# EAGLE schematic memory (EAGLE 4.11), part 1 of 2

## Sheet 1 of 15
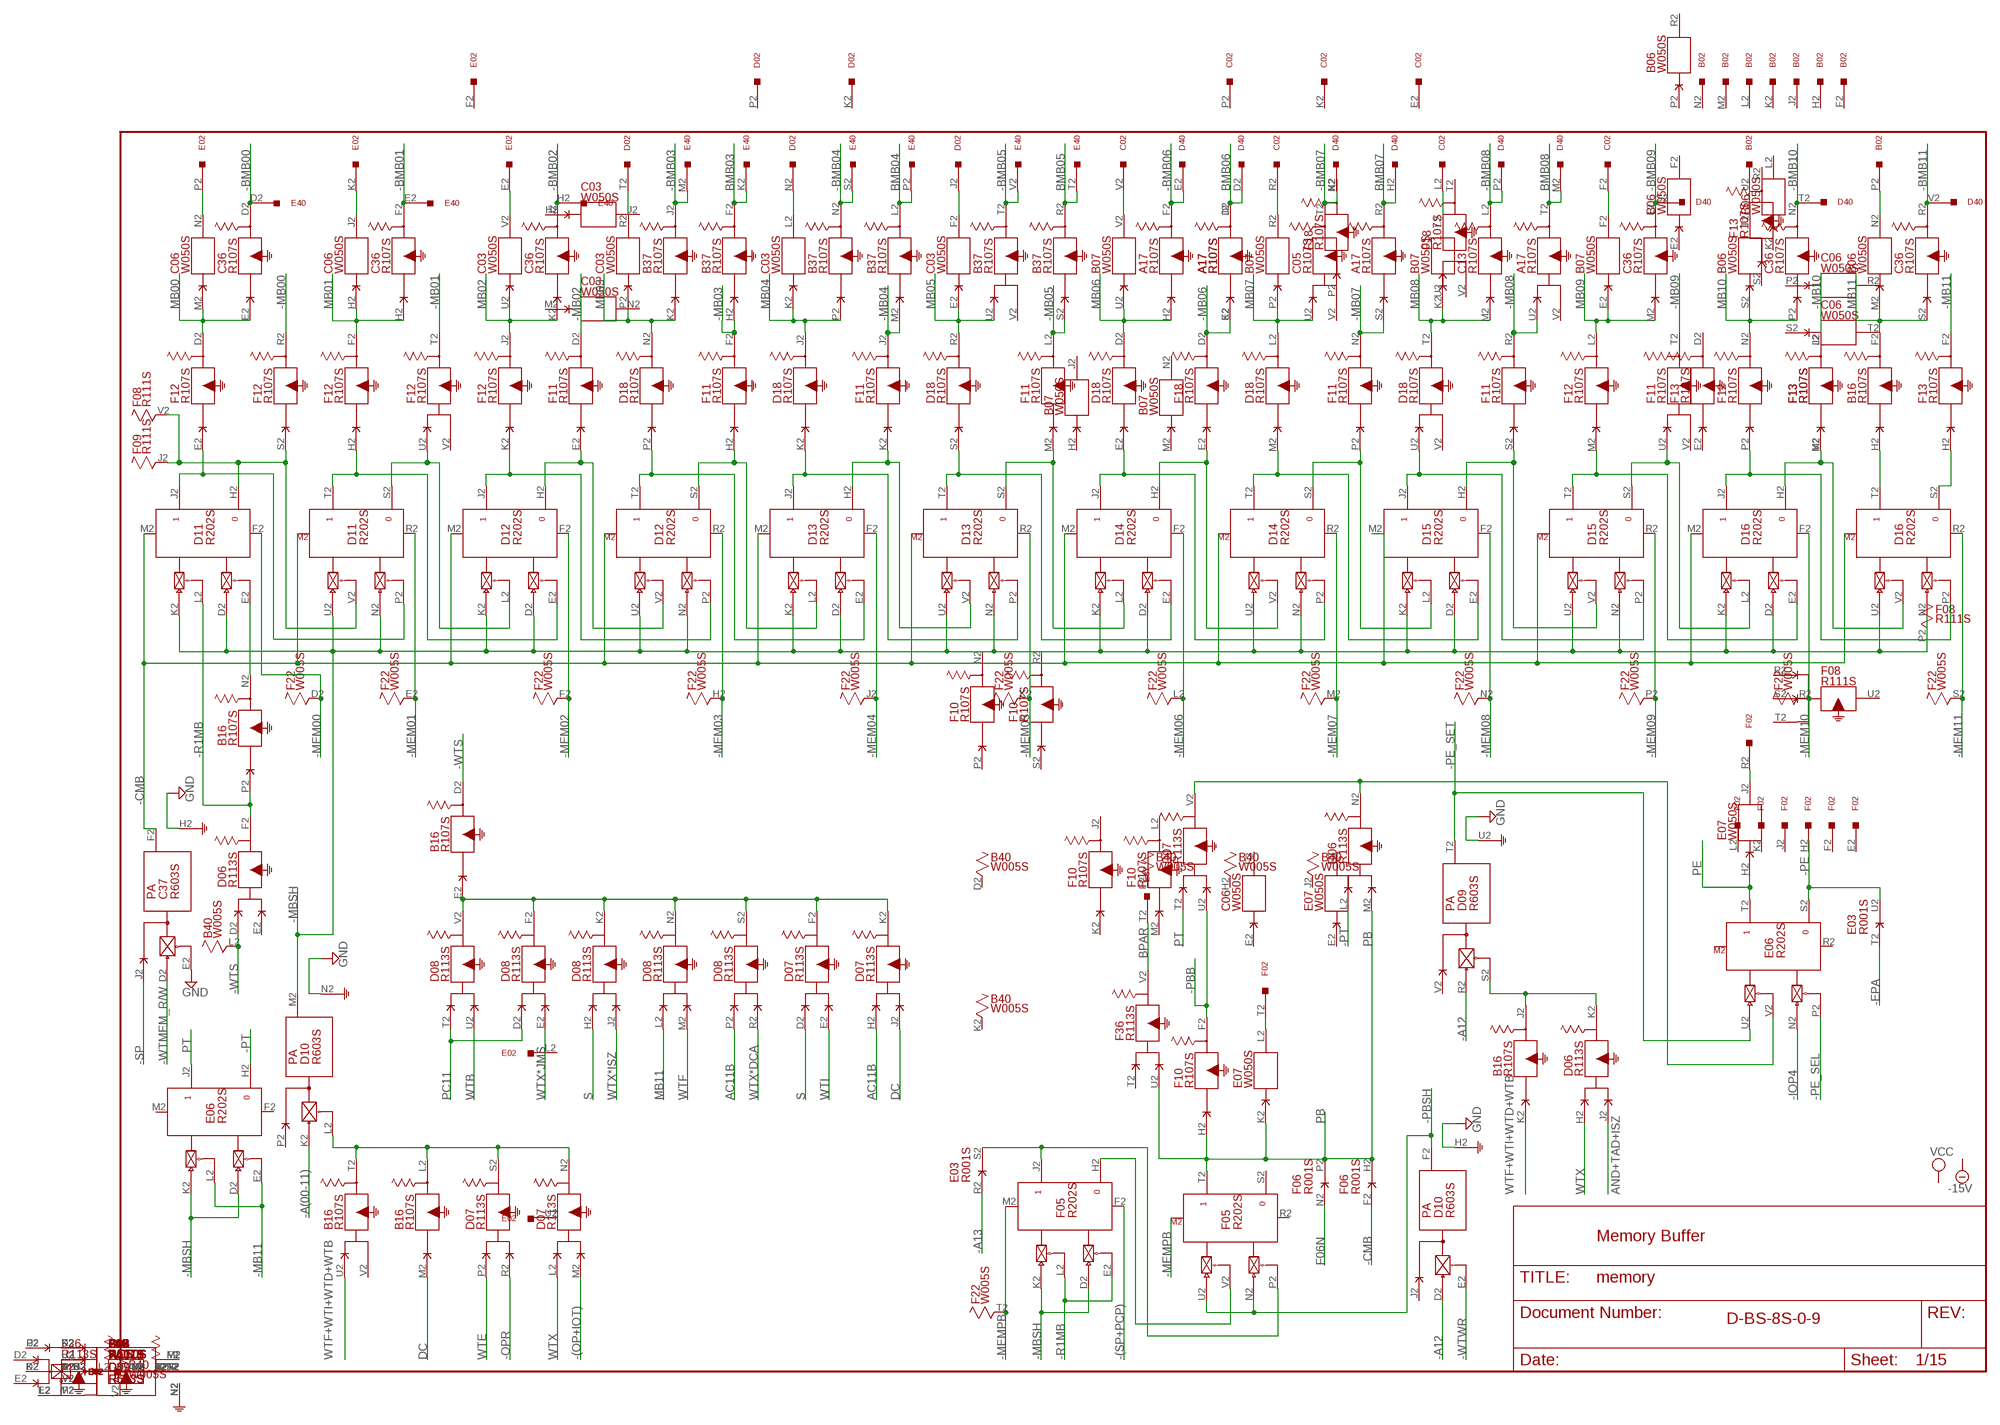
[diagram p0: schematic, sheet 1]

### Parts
A17  R107S  [H807S]
B02  W023S  [H807S]
B06  W050S  [H807S]
B07  W050S  [H807S]
B16  R107S  [H807S]
B37  R107S  [H807S]
B40  W005S  [H807S]
C02  W023S  [H807S]
C03  W050S  [H807S]
C05  R107S  [H807S]
C06  W050S  [H807S]
C13  R107S  [H807S]
C36  R107S  [H807S]
C37  R603S  [H807S]
D02  W023S  [H807S]
D06  R113S  [H807S]
D07  R113S  [H807S]
D08  R113S  [H807S]
D09  R603S  [H807S]
D10  R603S  [H807S]
D11  R202S  [H807S]
D12  R202S  [H807S]
D13  R202S  [H807S]
D14  R202S  [H807S]
D15  R202S  [H807S]
D16  R202S  [H807S]
D18  R107S  [H807S]
D40  W028S  [H807S]
E02  W023S  [H807S]
E03  R001S  [H807S]
E06  R202S  [H807S]
E07  W050S  [H807S]
E37  W028S  [H807S]
E40  W028S  [H807S]
F02  W023S  [H807S]
F05  R202S  [H807S]
F06  R001S  [H807S]
F08  R111S  [H807S]
F09  R111S  [H807S]
F10  R107S  [H807S]
F11  R107S  [H807S]
F12  R107S  [H807S]
F13  R107S  [H807S]
F18  R107S  [H807S]
F22  W005S  [H807S]
F36  R113S  [H807S]

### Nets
-(OP+IOT): D07.M2(N:I$2) ; also sheet 6,9
-(SP+PCP): F05.F2(J:RESET) ; also sheet 3,7,8,10,12,14,15
-A12: D09.R2(T:PU0) D10.D2(F:PU0) ; also sheet 3,4,6,8,10,12,15
-A13: E03.R2(S:D) ; also sheet 4,5,6,7,10,15
-A(00-11): D10.K2(M:PU0) ; also sheet 3,4,5,7,9,11,12
-BMB00: C36.D2(D:O$1) E40.D2
-BMB01: C36.F2(F:O$1) E40.E2
-BMB02: C36.J2(J:O$1) E40.H2
-BMB03: B37.J2(J:O$1) E40.M2
-BMB04: B37.N2(N:O$1) E40.S2
-BMB05: B37.T2(T:O$1) E40.V2
-BMB06: A17.F2(F:O$1) D40.E2
-BMB07: C05.T2(T:O$1) D40.K2
-BMB08: C13.L2(L:O$1) D40.P2
-BMB09: C36.L2(L:O$1) D40.S2
-BMB10: C36.N2(N:O$1) D40.T2
-BMB11: C36.R2(R:O$1) D40.V2
-CMB: C37.F2(F:O) D11.M2(J:SET) D12.M2(J:SET) D13.M2(J:SET) D14.M2(J:SET) D15.M2(J:SET) D16.M2(J:SET) F06.F2(H:D)
-EPA: E03.T2(U:D) ; also sheet 8
-IOP4: E06.N2(T:PU0) ; also sheet 10
-MB00: F12.R2(R:O$1) ; also sheet 2
-MB01: F12.T2(T:O$1) ; also sheet 2
-MB02: F11.D2(D:O$1) ; also sheet 2
-MB03: B37.H2(F:I$1) F11.F2(F:O$1) ; also sheet 2,10
-MB04: B37.M2(L:I$1) F11.J2(J:O$1) ; also sheet 2,5,10
-MB05: B37.S2(R:I$1) F11.L2(L:O$1) ; also sheet 2,6,10
-MB06: A17.E2(D:I$1) F18.D2(D:O$1) ; also sheet 2,6,7,10
-MB07: A17.S2(R:I$1) F11.N2(N:O$1) ; also sheet 2,6,10
-MB08: A17.U2(T:I$1) F11.R2(R:O$1) ; also sheet 2,3,10
-MB09: F11.T2(T:O$1) ; also sheet 2,10
-MB10: F13.L2(L:O$1) ; also sheet 2,9,10
-MB11: E06.E2(J:EN0) E06.L2(J:EN1) F13.F2(F:O$1) ; also sheet 2,9,10
-MBSH: D10.M2(M:O) D11.D2(J:PU0) D11.K2(J:PU1) D11.N2(T:PU0) D11.U2(T:PU1) D12.D2(J:PU0) D12.K2(J:PU1) D12.N2(T:PU0) D12.U2(T:PU1) D13.D2(J:PU0) D13.K2(J:PU1) D13.N2(T:PU0) D13.U2(T:PU1) D14.D2(J:PU0) D14.K2(J:PU1) D14.N2(T:PU0) D14.U2(T:PU1) D15.D2(J:PU0) D15.K2(J:PU1) D15.N2(T:PU0) D15.U2(T:PU1) D16.D2(J:PU0) D16.K2(J:PU1) D16.N2(T:PU0) D16.U2(T:PU1) E06.D2(J:PU0) E06.K2(J:PU1) F05.D2(J:PU0) F05.K2(J:PU1)
-MEM00: D11.F2(J:RESET) F22.D2 ; also sheet 2,15
-MEM01: D11.R2(T:RESET) F22.E2 ; also sheet 2,15
-MEM02: D12.F2(J:RESET) F22.F2 ; also sheet 2,15
-MEM03: D12.R2(T:RESET) F22.H2 ; also sheet 2,15
-MEM04: D13.F2(J:RESET) F22.J2 ; also sheet 2,15
-MEM05: D13.R2(T:RESET) F22.K2 ; also sheet 2,15
-MEM06: D14.F2(J:RESET) F22.L2 ; also sheet 2,15
-MEM07: D14.R2(T:RESET) F22.M2 ; also sheet 2,15
-MEM08: D15.F2(J:RESET) F22.N2 ; also sheet 2,15
-MEM09: D15.R2(T:RESET) F22.P2 ; also sheet 2,15
-MEM10: D16.F2(J:RESET) F22.R2 ; also sheet 2,15
-MEM11: D16.R2(T:RESET) F22.S2 ; also sheet 2,15
-MEMPB: F05.M2(J:SET) F22.T2 ; also sheet 2
-OPR: D07.R2(S:I$2) ; also sheet 9
-PBB: D07.U2(V:I$2) F10.F2(F:O$1) ; also sheet 2
-PBSH: D10.F2(F:O) F05.N2(T:PU0) F05.U2(T:PU1)
-PE: E03.U2(U:E) E06.S2 ; also sheet 10
-PE_SEL: E06.P2(T:EN0) ; also sheet 10
-PE_SET: D09.T2(T:O) E06.U2(T:PU1)
-PT: D06.L2(N:I$1) E06.H2
-R1MB: B16.P2(N:I$1) D06.F2(F:O$1) D11.L2(J:EN1) F05.E2(J:EN0) F05.L2(J:EN1)
-SP: C37.J2(F:I$1) ; also sheet 6,8
-WTMEM_R/W: C37.D2(F:PU0) ; also sheet 6,13
-WTS: B16.D2(D:O$1) B40.L2 D06.D2(F:I$1) ; also sheet 4,6
-WTWR: D10.E2(F:EN0) ; also sheet 6
AC11B: D07.H2(K:I$1) D08.P2(S:I$1) ; also sheet 7,12
AND+TAD+ISZ: D06.J2(K:I$2) ; also sheet 6,9
BMB03: B37.F2(F:O$1) E40.K2
BMB04: B37.L2(L:O$1) E40.P2
BMB05: B37.R2(R:O$1) E40.T2
BMB06: A17.D2(D:O$1) D40.D2
BMB07: A17.R2(R:O$1) D40.H2
BMB08: A17.T2(T:O$1) D40.M2
BPAR: E37.T2 F36.V2(V:O$1)
DC: B16.M2(L:I$1) D07.J2(K:I$2) ; also sheet 8,12
F06N: F06.N2(P:D)
GND [Supply]: C37.E2(F:EN0) C37.H2(F:G) D09.U2(T:G) D10.H2(F:G) D10.N2(M:G) ; also sheet 2,3,4,5,6,7,8,9,10,11,12,14,15
MB00: C06.M2(N:I$1) C36.E2(D:I$1) F12.D2(D:O$1)
MB01: C06.H2(J:I$1) C36.H2(F:I$1) F12.F2(F:O$1)
MB02: C03.U2(V:I$1) C36.K2(J:I$1) F12.J2(J:O$1)
MB03: B37.K2(J:I$1) C03.P2(R:I$1) D18.N2(N:O$1)
MB04: B37.P2(N:I$1) C03.K2(L:I$1) D18.J2(J:O$1) ; also sheet 12
MB05: B37.U2(T:I$1) C03.E2(F:I$1) D18.R2(R:O$1) ; also sheet 3,9,10
MB06: A17.H2(F:I$1) B07.U2(V:I$1) D18.D2(D:O$1) ; also sheet 3,7,9
MB07: B07.P2(R:I$1) C05.U2(T:I$1) D18.L2(L:O$1) ; also sheet 3,9
MB08: B07.K2(L:I$1) C13.M2(L:I$1) D18.T2(T:O$1) ; also sheet 3,6,9
MB09: B07.E2(F:I$1) C36.M2(L:I$1) F12.L2(L:O$1) ; also sheet 3,9
MB10: B06.S2(T:I$1) C36.P2(N:I$1) F12.N2(N:O$1) ; also sheet 8,9
MB11: B06.M2(N:I$1) B16.F2(F:O$1) C36.S2(R:I$1) D08.L2(N:I$1) ; also sheet 5,6,7,9,12
N$1: D11.J2 D11.P2(T:EN0) F12.E2(D:I$1)
N$2: C06.N2(N:O$1) E02.P2
N$3: D11.H2 D11.V2(T:EN1) F08.V2 F09.J2 F12.S2(R:I$1)
N$4: D11.T2 D12.E2(J:EN0) F12.H2(F:I$1)
N$5: B16.E2(D:I$1) D07.F2(F:O$1) D07.K2(K:O$1) D08.F2(F:O$1) D08.K2(K:O$1) D08.N2(N:O$1) D08.S2(S:O$1) D08.V2(V:O$1)
N$6: D12.J2 D12.P2(T:EN0) F12.K2(J:I$1)
N$7: D12.T2 D13.E2(J:EN0) D18.P2(N:I$1)
N$8: D13.J2 D13.P2(T:EN0) D18.K2(J:I$1)
N$9: D13.T2 D14.E2(J:EN0) D18.S2(R:I$1)
N$10: D14.J2 D14.P2(T:EN0) D18.E2(D:I$1)
N$11: D14.T2 D15.E2(J:EN0) D18.M2(L:I$1)
N$12: D15.J2 D15.P2(T:EN0) D18.U2(T:I$1)
N$13: D15.H2 D15.V2(T:EN1) F11.S2(R:I$1)
N$14: D14.S2 D15.L2(J:EN1) F11.P2(N:I$1)
N$15: D14.H2 D14.V2(T:EN1) F18.E2(D:I$1)
N$16: D13.S2 D14.L2(J:EN1) F11.M2(L:I$1)
N$17: D15.T2 D16.E2(J:EN0) F12.M2(L:I$1)
N$18: D15.S2 D16.L2(J:EN1) F11.U2(T:I$1)
N$19: D16.J2 D16.P2(T:EN0) F12.P2(N:I$1)
N$20: D13.H2 D13.V2(T:EN1) F11.K2(J:I$1)
N$21: D12.S2 D13.L2(J:EN1) F11.H2(F:I$1)
N$22: D12.H2 D12.V2(T:EN1) F11.E2(D:I$1)
N$23: D11.S2 D12.L2(J:EN1) F12.U2(T:I$1)
N$24: D16.H2 D16.V2(T:EN1) F13.M2(L:I$1)
N$25: B16.H2(F:I$1) D16.T2
N$26: D16.S2 F13.H2(F:I$1)
N$27: C06.J2(J:O$1) E02.K2
N$28: C03.V2(V:O$1) E02.E2
N$29: C03.R2(R:O$1) D02.T2
N$30: C03.L2(L:O$1) D02.N2
N$31: C03.F2(F:O$1) D02.J2
N$32: B07.V2(V:O$1) C02.V2
N$33: B07.R2(R:O$1) C02.R2
N$34: B07.L2(L:O$1) C02.L2
N$35: B07.F2(F:O$1) C02.F2
N$36: B02.U2 B06.T2(T:O$1)
N$37: B02.P2 B06.N2(N:O$1)
N$38: B16.L2(L:O$1) B16.T2(T:O$1) D07.N2(N:O$1) D07.S2(S:O$1) D10.L2(M:EN0)
N$39: B16.N2(N:O$1) D11.E2(J:EN0)
N$40: B16.J2(J:O$1) D06.K2(K:O$1) D09.S2(T:EN0)
N$41: E07.J2(J:O$1) F02.R2
N$42: D06.N2(N:O$1) D07.V2(V:O$1) E06.V2(T:EN1)
N$44: E07.L2(L:O$1) F02.T2
N$46: F05.H2 F05.V2(T:EN1)
N$47: E03.S2(S:E) F05.J2 F05.P2(T:EN0)
PB: D06.M2(N:I$2) E07.K2(L:I$1) F05.T2 F06.H2(H:E) F06.P2(P:E) F10.H2(F:I$1) F36.U2(V:I$2)
PC11: D08.D2(F:I$1) D08.T2(V:I$1) ; also sheet 5,7,11
PE: E06.T2 E07.H2(J:I$1) ; also sheet 10
PT: D07.T2(V:I$1) E06.J2
S: D07.D2(F:I$1) D08.H2(K:I$1) ; also sheet 5,7,11,12
WTB: D08.U2(V:I$2) ; also sheet 6
WTE: D07.P2(S:I$1) ; also sheet 3,6,8
WTF: D08.M2(N:I$2) ; also sheet 3,5,6,8,10,12
WTF+WTI+WTD+WTB: B16.K2(J:I$1) B16.U2(T:I$1) ; also sheet 6
WTI: D07.E2(F:I$2) ; also sheet 6
WTX: D06.H2(K:I$1) D07.L2(N:I$1) ; also sheet 3,6,7,10,12,15
WTX*DCA: D08.R2(S:I$2) ; also sheet 6
WTX*ISZ: D08.J2(K:I$2) ; also sheet 6
WTX*JMS: D08.E2(F:I$2) ; also sheet 6
Unconnected: B02.A2 B02.B2 B02.C2 B02.S2 B40.R2 C02.A2 C02.B2 C02.C2 C02.D2 C02.J2 C02.N2 C02.T2 C36.T2(T:O$1) C36.U2(T:I$1) C36.V2(T:I$2) D02.A2 D02.B2 D02.C2 D02.D2 D02.H2 D02.M2 D02.S2 D02.V2 E02.A2 E02.B2 E02.C2 E02.J2 E02.N2 E06.F2(J:RESET) E06.M2(J:SET) E06.R2(T:RESET) E07.P2(R:I$1) E07.R2(R:O$1) E07.S2(T:I$1) E07.T2(T:O$1) F02.A2 F02.B2 F02.C2 F02.N2 F02.P2 F02.S2 F02.U2 F05.R2(T:RESET) F05.S2 F11.V2(T:I$2) F12.V2(T:I$2) F22.V2

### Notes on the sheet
- Memory Buffer
- D-BS-8S-0-9

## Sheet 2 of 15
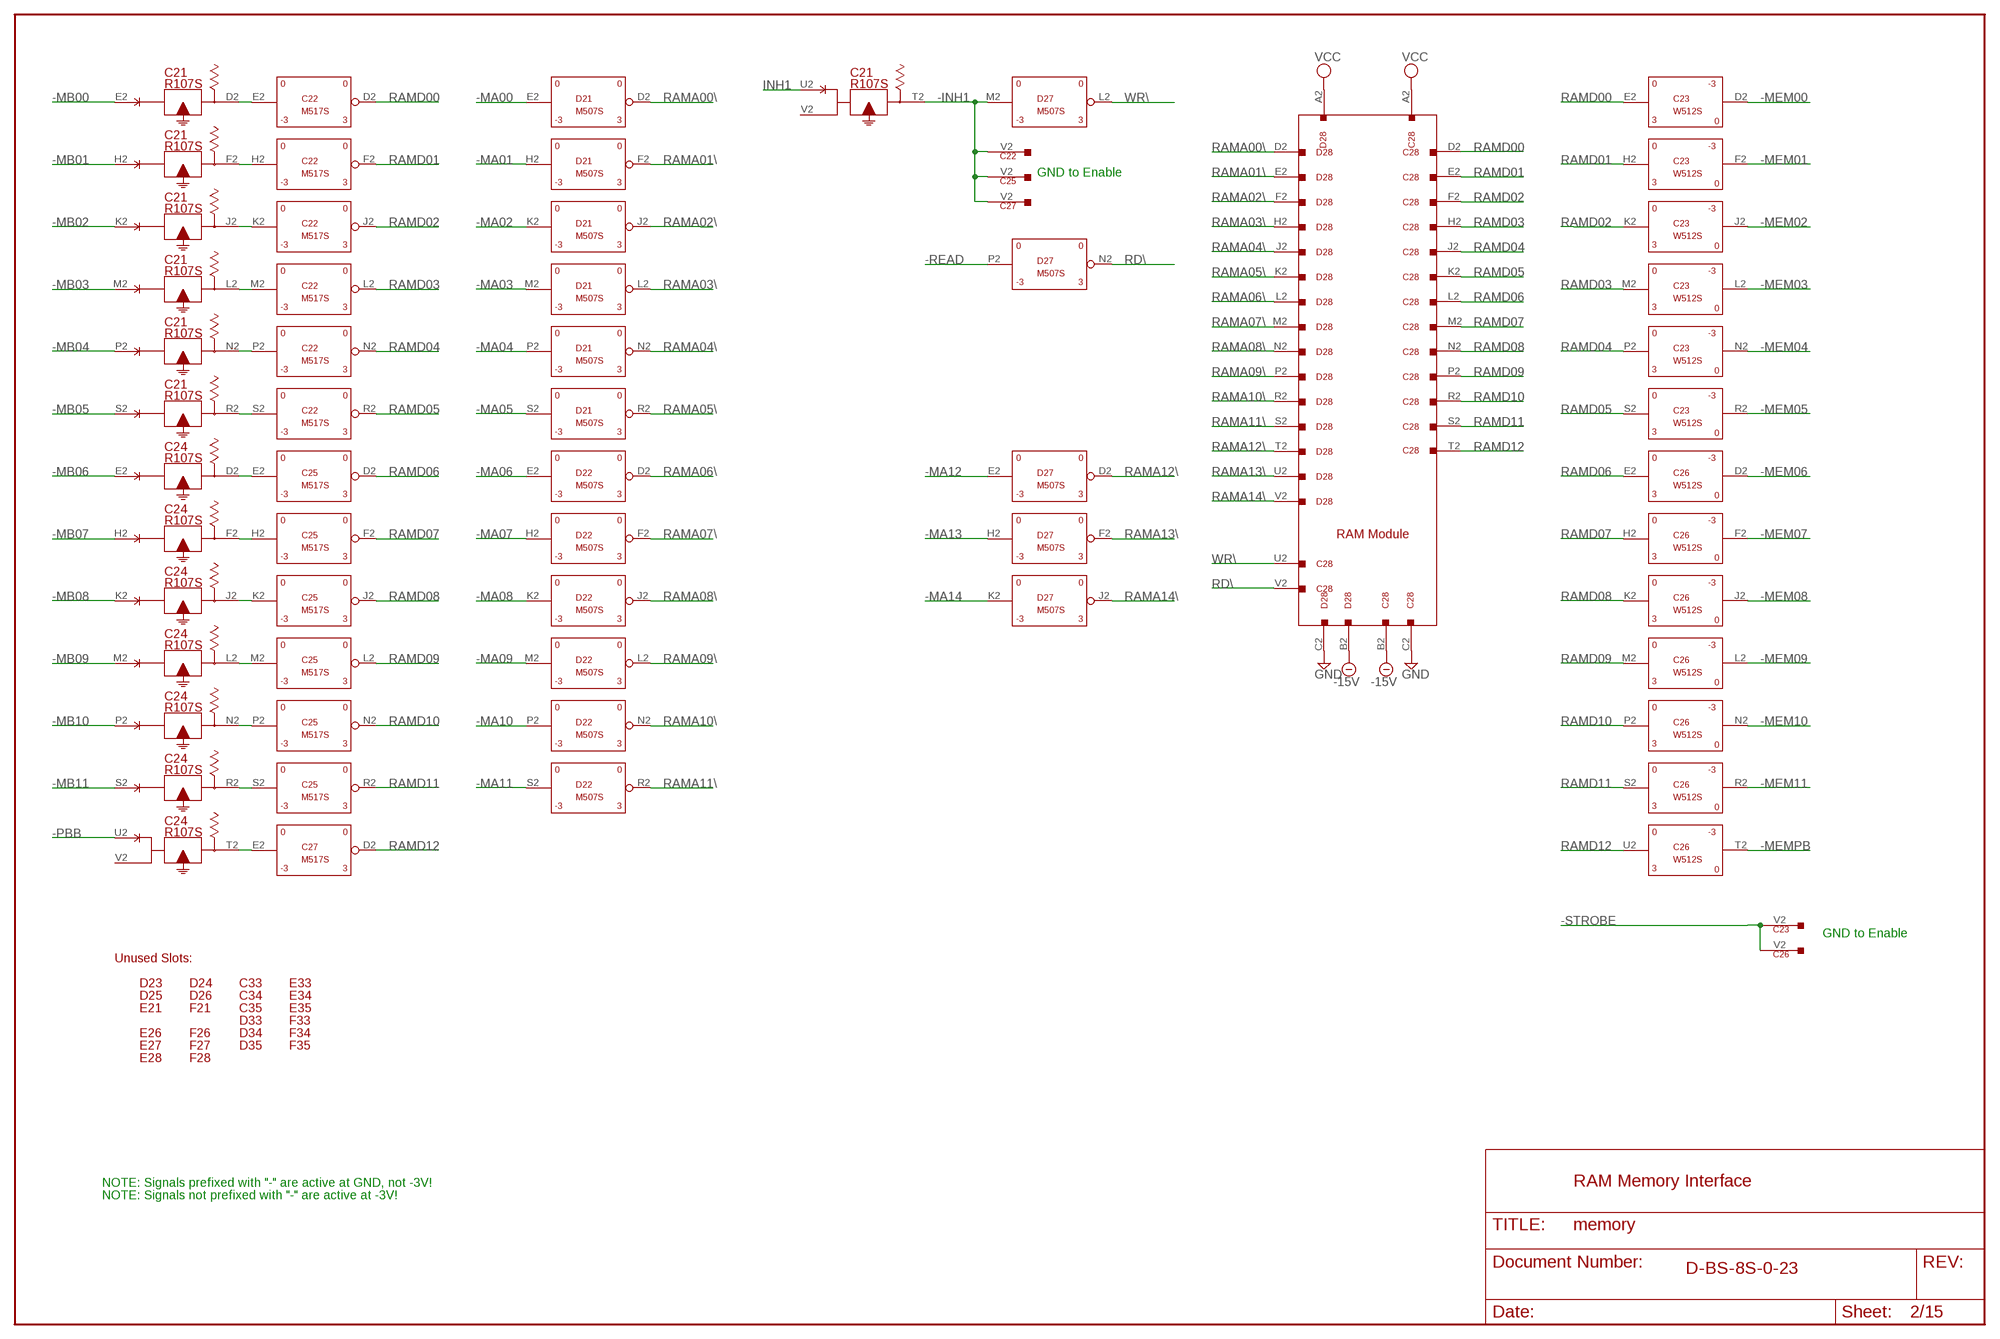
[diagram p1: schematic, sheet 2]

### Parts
C21  R107S  [H807S]
C22  M517S  [H807S]
C23  W512S  [H807S]
C24  R107S  [H807S]
C25  M517S  [H807S]
C26  W512S  [H807S]
C27  M517S  [H807S]
C28  W023S  [H807S]
C33  EMPTYS  [H807S]
C34  EMPTYS  [H807S]
C35  EMPTYS  [H807S]
D21  M507S  [H807S]
D22  M507S  [H807S]
D23  EMPTYS  [H807S]
D24  EMPTYS  [H807S]
D25  EMPTYS  [H807S]
D26  EMPTYS  [H807S]
D27  M507S  [H807S]
D28  W023S  [H807S]
D33  EMPTYS  [H807S]
D34  EMPTYS  [H807S]
D35  EMPTYS  [H807S]
E21  EMPTYS  [H807S]
E26  EMPTYS  [H807S]
E27  EMPTYS  [H807S]
E28  EMPTYS  [H807S]
E33  EMPTYS  [H807S]
E34  EMPTYS  [H807S]
E35  EMPTYS  [H807S]
F21  EMPTYS  [H807S]
F26  EMPTYS  [H807S]
F27  EMPTYS  [H807S]
F28  EMPTYS  [H807S]
F33  EMPTYS  [H807S]
F34  EMPTYS  [H807S]
F35  EMPTYS  [H807S]

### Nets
-15V [Supply]: C28.B2 D28.B2
-INH1: C21.T2(T:O$1) C22.V2 C25.V2 C27.V2 D27.M2(L:IN)
-MA00: D21.E2(D:IN) ; also sheet 5,15
-MA01: D21.H2(F:IN) ; also sheet 5,15
-MA02: D21.K2(J:IN) ; also sheet 5,15
-MA03: D21.M2(L:IN) ; also sheet 5,15
-MA04: D21.P2(N:IN) ; also sheet 5,6,15
-MA05: D21.S2(R:IN) ; also sheet 5,15
-MA06: D22.E2(D:IN) ; also sheet 5,15
-MA07: D22.H2(F:IN) ; also sheet 5,15
-MA08: D22.K2(J:IN) ; also sheet 5,15
-MA09: D22.M2(L:IN) ; also sheet 5,15
-MA10: D22.P2(N:IN) ; also sheet 5,15
-MA11: D22.S2(R:IN) ; also sheet 5,15
-MA12: D27.E2(D:IN)
-MA13: D27.H2(F:IN)
-MA14: D27.K2(J:IN)
-MB00: C21.E2(D:I$1) ; also sheet 1
-MB01: C21.H2(F:I$1) ; also sheet 1
-MB02: C21.K2(J:I$1) ; also sheet 1
-MB03: C21.M2(L:I$1) ; also sheet 1,10
-MB04: C21.P2(N:I$1) ; also sheet 1,5,10
-MB05: C21.S2(R:I$1) ; also sheet 1,6,10
-MB06: C24.E2(D:I$1) ; also sheet 1,6,7,10
-MB07: C24.H2(F:I$1) ; also sheet 1,6,10
-MB08: C24.K2(J:I$1) ; also sheet 1,3,10
-MB09: C24.M2(L:I$1) ; also sheet 1,10
-MB10: C24.P2(N:I$1) ; also sheet 1,9,10
-MB11: C24.S2(R:I$1) ; also sheet 1,9,10
-MEM00: C23.D2(OUT) ; also sheet 1,15
-MEM01: C23.F2(OUT) ; also sheet 1,15
-MEM02: C23.J2(OUT) ; also sheet 1,15
-MEM03: C23.L2(OUT) ; also sheet 1,15
-MEM04: C23.N2(OUT) ; also sheet 1,15
-MEM05: C23.R2(OUT) ; also sheet 1,15
-MEM06: C26.D2(OUT) ; also sheet 1,15
-MEM07: C26.F2(OUT) ; also sheet 1,15
-MEM08: C26.J2(OUT) ; also sheet 1,15
-MEM09: C26.L2(OUT) ; also sheet 1,15
-MEM10: C26.N2(OUT) ; also sheet 1,15
-MEM11: C26.R2(OUT) ; also sheet 1,15
-MEMPB: C26.T2(OUT) ; also sheet 1
-PBB: C24.U2(T:I$1) ; also sheet 1
-READ: D27.P2(N:IN) ; also sheet 13
-STROBE: C23.V2 C26.V2 ; also sheet 13
GND [Supply]: C28.C2 D28.C2 ; also sheet 1,3,4,5,6,7,8,9,10,11,12,14,15
INH1: C21.U2(T:I$1) ; also sheet 13
N$49: C24.D2(D:O$1) C25.E2(D:IN)
N$50: C21.R2(R:O$1) C22.S2(R:IN)
N$51: C21.N2(N:O$1) C22.P2(N:IN)
N$52: C21.L2(L:O$1) C22.M2(L:IN)
N$55: C21.J2(J:O$1) C22.K2(J:IN)
N$56: C21.F2(F:O$1) C22.H2(F:IN)
N$57: C21.D2(D:O$1) C22.E2(D:IN)
N$58: C24.F2(F:O$1) C25.H2(F:IN)
N$59: C24.J2(J:O$1) C25.K2(J:IN)
N$60: C24.L2(L:O$1) C25.M2(L:IN)
N$61: C24.N2(N:O$1) C25.P2(N:IN)
N$62: C24.R2(R:O$1) C25.S2(R:IN)
N$63: C24.T2(T:O$1) C27.E2(D:IN)
RAMA00\: D21.D2(D:OUT) D28.D2
RAMA01\: D21.F2(F:OUT) D28.E2
RAMA02\: D21.J2(J:OUT) D28.F2
RAMA03\: D21.L2(L:OUT) D28.H2
RAMA04\: D21.N2(N:OUT) D28.J2
RAMA05\: D21.R2(R:OUT) D28.K2
RAMA06\: D22.D2(D:OUT) D28.L2
RAMA07\: D22.F2(F:OUT) D28.M2
RAMA08\: D22.J2(J:OUT) D28.N2
RAMA09\: D22.L2(L:OUT) D28.P2
RAMA10\: D22.N2(N:OUT) D28.R2
RAMA11\: D22.R2(R:OUT) D28.S2
RAMA12\: D27.D2(D:OUT) D28.T2
RAMA13\: D27.F2(F:OUT) D28.U2
RAMA14\: D27.J2(J:OUT) D28.V2
RAMD00: C22.D2(D:OUT) C23.E2(IN) C28.D2
RAMD01: C22.F2(F:OUT) C23.H2(IN) C28.E2
RAMD02: C22.J2(J:OUT) C23.K2(IN) C28.F2
RAMD03: C22.L2(L:OUT) C23.M2(IN) C28.H2
RAMD04: C22.N2(N:OUT) C23.P2(IN) C28.J2
RAMD05: C22.R2(R:OUT) C23.S2(IN) C28.K2
RAMD06: C25.D2(D:OUT) C26.E2(IN) C28.L2
RAMD07: C25.F2(F:OUT) C26.H2(IN) C28.M2
RAMD08: C25.J2(J:OUT) C26.K2(IN) C28.N2
RAMD09: C25.L2(L:OUT) C26.M2(IN) C28.P2
RAMD10: C25.N2(N:OUT) C26.P2(IN) C28.R2
RAMD11: C25.R2(R:OUT) C26.S2(IN) C28.S2
RAMD12: C26.U2(IN) C27.D2(D:OUT) C28.T2
RD\: C28.V2 D27.N2(N:OUT)
VCC [Supply]: C28.A2 D28.A2
WR\: C28.U2 D27.L2(L:OUT)
Unconnected: C21.V2(T:I$2) C23.T2(OUT) C23.U2(IN) C24.V2(T:I$2) C27.F2(F:OUT) C27.H2(F:IN) C27.J2(J:OUT) C27.K2(J:IN) C27.L2(L:OUT) C27.M2(L:IN) C27.N2(N:OUT) C27.P2(N:IN) C27.R2(R:OUT) C27.S2(R:IN) D27.R2(R:OUT) D27.S2(R:IN)

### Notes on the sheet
- GND to Enable
- RAM Module
- GND to Enable
- Unused Slots:
- NOTE: Signals prefixed with "-" are active at GND, not -3V! | RAM Memory Interface
- NOTE: Signals not prefixed with "-" are active at -3V!
- D-BS-8S-0-23

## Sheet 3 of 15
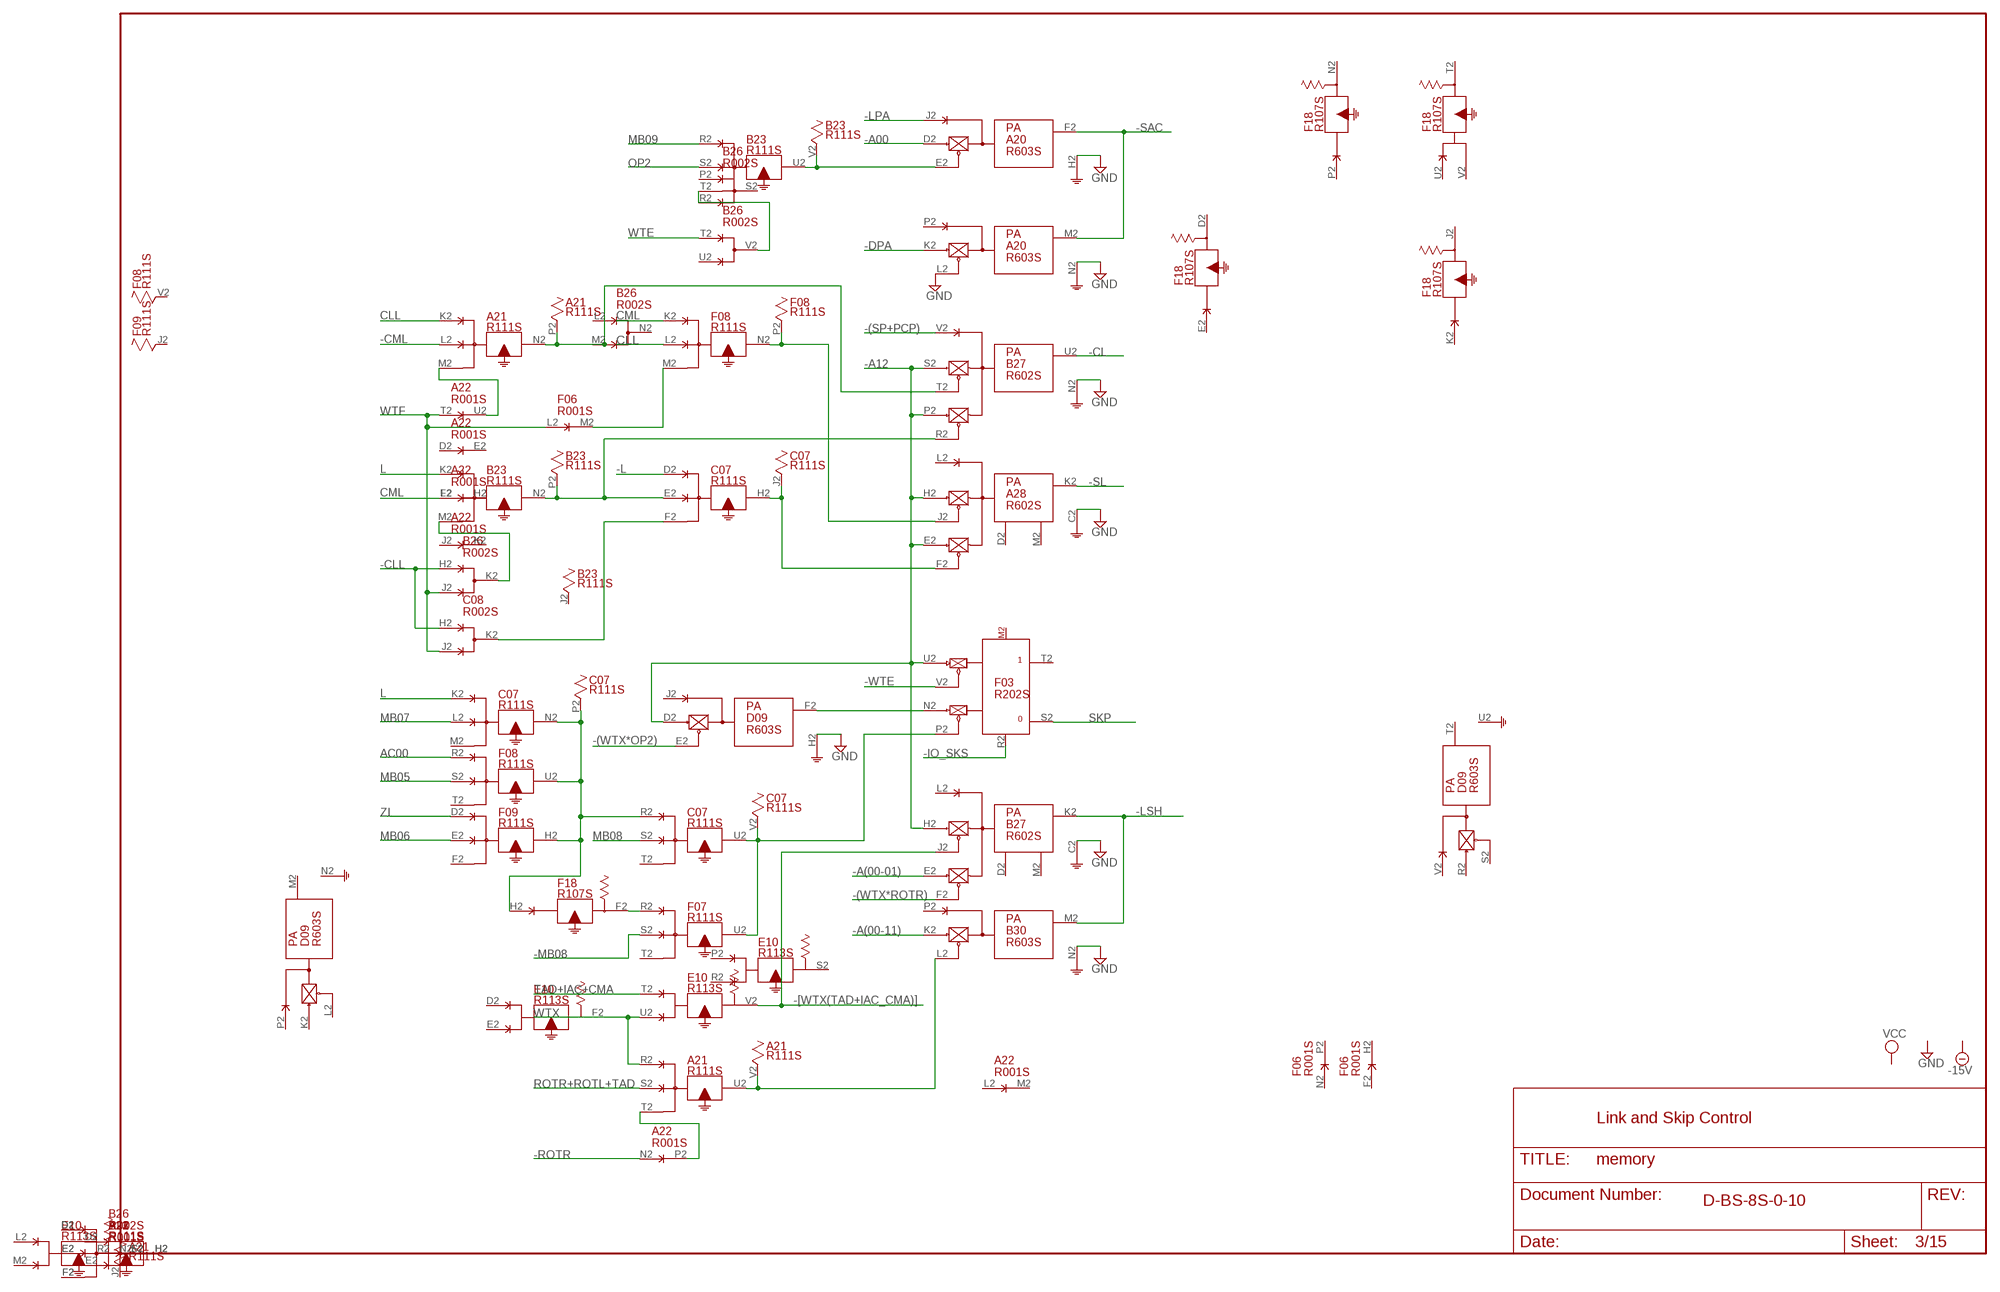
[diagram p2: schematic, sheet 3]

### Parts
A20  R603S  [H807S]
A21  R111S  [H807S]
A22  R001S  [H807S]
A28  R602S  [H807S]
B23  R111S  [H807S]
B26  R002S  [H807S]
B27  R602S  [H807S]
B30  R603S  [H807S]
C07  R111S  [H807S]
C08  R002S  [H807S]
E10  R113S  [H807S]
F03  R202S  [H807S]
F07  R111S  [H807S]

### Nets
-(SP+PCP): B27.V2(U:L) ; also sheet 1,7,8,10,12,14,15
-(WTX*OP2): D09.E2(F:EN0) ; also sheet 6,7
-(WTX*ROTR): B27.F2(K:F) ; also sheet 6,12
-[WTX(TAD+IAC_CMA)]: B27.J2(K:J) E10.V2(V:O$1)
-A00: A20.D2(F:PU0) ; also sheet 4,5,9,10,14,15
-A12: A28.E2(K:E) A28.H2(K:H) B27.H2(K:H) B27.P2(U:E) B27.S2(U:H) D09.D2(F:PU0) F03.U2(T:PU1) ; also sheet 1,4,6,8,10,12,15
-A(00-01): B27.E2(K:E) ; also sheet 4,12
-A(00-11): B30.K2(M:PU0) ; also sheet 1,4,5,7,9,11,12
-CL: B27.U2(U:K) ; also sheet 12
-CLL: B26.H2(K:D) C08.H2(K:D) ; also sheet 9
-CML: A21.L2(N:I$2) ; also sheet 9
-DPA: A20.K2(M:PU0) ; also sheet 8
-IO_SKS: F03.R2(T:RESET) ; also sheet 10
-L: C07.D2(H:I$1) ; also sheet 12
-LPA: A20.J2(F:I$1) ; also sheet 8
-LSH: B27.K2(K:K) B30.M2(M:O) ; also sheet 12
-MB08: F07.S2(U:I$2) ; also sheet 1,2,10
-ROTR: A22.N2(P:D) ; also sheet 9
-SAC: A20.F2(F:O) A20.M2(M:O) ; also sheet 8
-SL: A28.K2(K:K) ; also sheet 12
-WTE: F03.V2(T:EN1) ; also sheet 6
AC00: F08.R2(U:I$1) ; also sheet 12
CLL: A21.K2(N:I$1) F08.L2(N:I$2) ; also sheet 9
CML: B23.L2(N:I$2) F08.K2(N:I$1) ; also sheet 9
GND [Supply]: A20.H2(F:G) A20.L2(M:EN0) A20.N2(M:G) A28.C2(K:GND) B27.C2(K:GND) B27.N2(U:C) B30.N2(M:G) D09.H2(F:G) ; also sheet 1,2,4,5,6,7,8,9,10,11,12,14,15
L: B23.K2(N:I$1) C07.K2(N:I$1) ; also sheet 7,12
MB05: F08.S2(U:I$2) ; also sheet 1,9,10
MB06: F09.E2(H:I$2) ; also sheet 1,7,9
MB07: C07.L2(N:I$2) ; also sheet 1,9
MB08: C07.S2(U:I$2) ; also sheet 1,6,9
MB09: B23.R2(U:I$1) ; also sheet 1,9
N$48: A20.E2(F:EN0) B23.U2(U:O$1) B23.V2
N$53: B23.T2(U:I$3) B26.V2(V:F)
N$54: A28.J2(K:J) F08.N2(N:O$1) F08.P2
N$64: A21.N2(N:O$1) A21.P2 B27.T2(U:J)
N$65: B23.N2(N:O$1) B23.P2 B27.R2(U:F) C07.E2(H:I$2)
N$66: A28.F2(K:F) C07.H2(H:O$1) C07.J2
N$67: B23.M2(N:I$3) B26.K2(K:F)
N$68: F06.M2(M:E) F08.M2(N:I$3)
N$69: C07.F2(H:I$3) C08.K2(K:F)
N$71: D09.F2(F:O) F03.N2(T:PU0)
N$72: C07.U2(U:O$1) C07.V2 F03.P2(T:EN0) F07.U2(U:O$1)
N$73: F07.R2(U:I$1) F18.F2(F:O$1)
N$74: C07.N2(N:O$1) C07.P2 C07.R2(U:I$1) F08.U2(U:O$1) F09.H2(H:O$1) F18.H2(F:I$1)
N$75: A21.U2(U:O$1) A21.V2 B30.L2(M:EN0)
N$76: A21.T2(U:I$3) A22.P2(P:E)
N$79: A21.M2(N:I$3) A22.U2(U:E)
OP2: B23.S2(U:I$2) ; also sheet 6,7,8,9,12
ROTR+ROTL+TAD: A21.S2(U:I$2) ; also sheet 9,12
SKP: F03.S2 ; also sheet 9
TAD+IAC+CMA: E10.T2(V:I$1) ; also sheet 9,12
WTE: B26.T2(V:D) ; also sheet 1,6,8
WTF: A22.T2(U:D) B26.J2(K:E) C08.J2(K:E) F06.L2(M:D) ; also sheet 1,5,6,8,10,12
WTX: A21.R2(U:I$1) E10.U2(V:I$2) ; also sheet 1,6,7,10,12,15
ZI: F09.D2(H:I$1) ; also sheet 7,9
Unconnected: B27.D2(K:D) B27.L2(K:L) B27.M2(K:M) C07.M2(N:I$3) C07.T2(U:I$3) C08.L2(N:D) C08.M2(N:E) C08.N2(N:F) F07.P2 F07.V2

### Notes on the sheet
- Link and Skip Control
- D-BS-8S-0-10

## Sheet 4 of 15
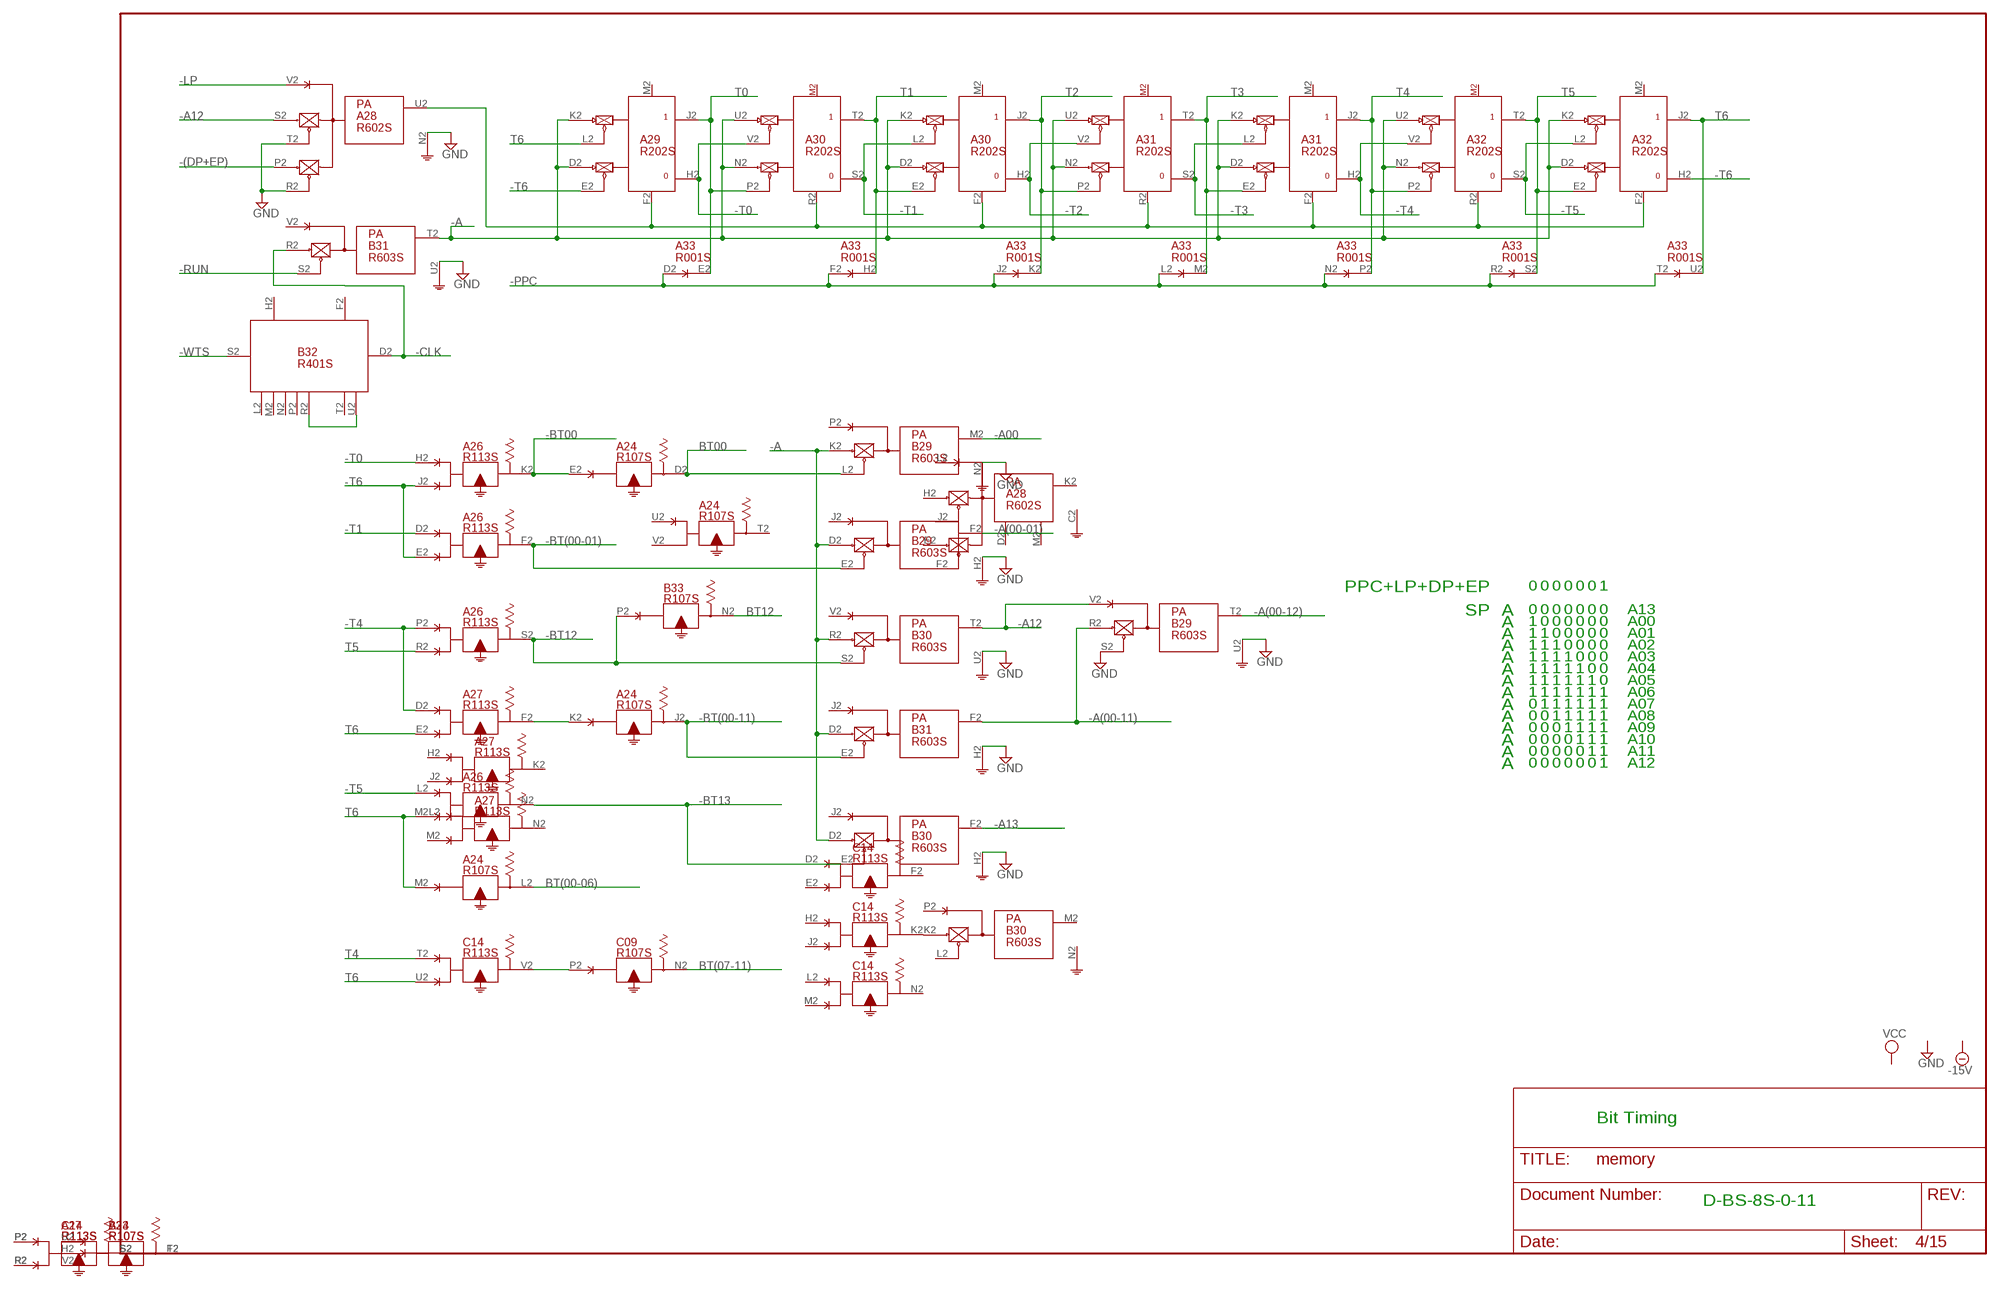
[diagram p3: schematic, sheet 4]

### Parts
A24  R107S  [H807S]
A26  R113S  [H807S]
A27  R113S  [H807S]
A29  R202S  [H807S]
A30  R202S  [H807S]
A31  R202S  [H807S]
A32  R202S  [H807S]
A33  R001S  [H807S]
B29  R603S  [H807S]
B31  R603S  [H807S]
B32  R401S  [H807S]
B33  R107S  [H807S]
C09  R107S  [H807S]
C14  R113S  [H807S]

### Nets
-(DP+EP): A28.P2(U:E) ; also sheet 6,8,12
-A: A29.D2(J:PU0) A29.K2(J:PU1) A30.D2(J:PU0) A30.K2(J:PU1) A30.N2(T:PU0) A30.U2(T:PU1) A31.D2(J:PU0) A31.K2(J:PU1) A31.N2(T:PU0) A31.U2(T:PU1) A32.D2(J:PU0) A32.K2(J:PU1) A32.N2(T:PU0) A32.U2(T:PU1) B29.D2(F:PU0) B29.K2(M:PU0) B30.D2(F:PU0) B30.R2(T:PU0) B31.D2(F:PU0) B31.T2(T:O) ; also sheet 15
-A00: B29.M2(M:O) ; also sheet 3,5,9,10,14,15
-A12: A28.S2(U:H) B29.V2(T:I$1) B30.T2(T:O) ; also sheet 1,3,6,8,10,12,15
-A13: B30.F2(F:O) ; also sheet 1,5,6,7,10,15
-A(00-01): B29.F2(F:O) ; also sheet 3,12
-A(00-11): B29.R2(T:PU0) B31.F2(F:O) ; also sheet 1,3,5,7,9,11,12
-A(00-12): B29.T2(T:O) ; also sheet 7
-BT00: A24.E2(D:I$1) A26.K2(K:O$1)
-BT12: A26.S2(S:O$1) B30.S2(T:EN0) B33.P2(N:I$1) ; also sheet 7
-BT13: A26.N2(N:O$1) B30.E2(F:EN0)
-BT(00-01): A26.F2(F:O$1) B29.E2(F:EN0)
-BT(00-11): A24.J2(J:O$1) B31.E2(F:EN0)
-CLK: B31.R2(T:PU0) B32.D2(D) ; also sheet 8,15
-LP: A28.V2(U:L) ; also sheet 6,8,12,15
-PPC: A33.D2(E:D) A33.F2(H:D) A33.J2(K:D) A33.L2(M:D) A33.N2(P:D) A33.R2(S:D) A33.T2(U:D) ; also sheet 6,8,10,11,15
-RUN: B31.S2(T:EN0) ; also sheet 8,10
-T0: A26.H2(K:I$1) A29.H2 A30.V2(T:EN1)
-T1: A26.D2(F:I$1) A30.L2(J:EN1) A30.S2
-T2: A30.H2 A31.V2(T:EN1)
-T3: A31.L2(J:EN1) A31.S2 ; also sheet 15
-T4: A26.P2(S:I$1) A27.D2(F:I$1) A31.H2 A32.V2(T:EN1)
-T5: A26.L2(N:I$1) A32.L2(J:EN1) A32.S2
-T6: A26.E2(F:I$2) A26.J2(K:I$2) A29.E2(J:EN0) A32.H2
-WTS: B32.S2(S) ; also sheet 1,6
BT00: A24.D2(D:O$1) B29.L2(M:EN0) ; also sheet 7,9,15
BT12: B33.N2(N:O$1) ; also sheet 7
BT(00-06): A24.L2(L:O$1) ; also sheet 6
BT(07-11): C09.N2(N:O$1) ; also sheet 6
GND [Supply]: A28.N2(U:C) A28.R2(U:F) A28.T2(U:J) B29.H2(F:G) B29.N2(M:G) B29.S2(T:EN0) B29.U2(T:G) B30.H2(F:G) B30.U2(T:G) B31.H2(F:G) B31.U2(T:G) ; also sheet 1,2,3,5,6,7,8,9,10,11,12,14,15
N$77: A24.K2(J:I$1) A27.F2(F:O$1)
N$78: C09.P2(N:I$1) C14.V2(V:O$1)
N$88: B32.R2(R) B32.U2(U)
N$94: A28.U2(U:K) A29.F2(J:RESET) A30.F2(J:RESET) A30.R2(T:RESET) A31.F2(J:RESET) A31.R2(T:RESET) A32.F2(J:RESET) A32.R2(T:RESET)
T0: A29.J2 A30.P2(T:EN0) A33.E2(E:E)
T1: A30.E2(J:EN0) A30.T2 A33.H2(H:E)
T2: A30.J2 A31.P2(T:EN0) A33.K2(K:E)
T3: A31.E2(J:EN0) A31.T2 A33.M2(M:E)
T4: A31.J2 A32.P2(T:EN0) A33.P2(P:E) C14.T2(V:I$1) ; also sheet 15
T5: A26.R2(S:I$2) A32.E2(J:EN0) A32.T2 A33.S2(S:E)
T6: A24.M2(L:I$1) A26.M2(N:I$2) A27.E2(F:I$2) A29.L2(J:EN1) A32.J2 A33.U2(U:E) C14.U2(V:I$2)
Unconnected: A28.D2(K:D) A28.L2(K:L) A28.M2(K:M) A29.M2(J:SET) A30.M2(J:SET) A31.M2(J:SET) A32.M2(J:SET) B29.J2(F:I$1) B29.P2(M:I$1) B30.J2(F:I$1) B30.P2(M:I$1) B30.V2(T:I$1) B31.J2(F:I$1) B31.V2(T:I$1) B32.F2(F) B32.H2(H) B32.L2(L) B32.M2(M) B32.N2(N) B32.P2(P) B32.T2(T)

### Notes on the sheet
- PPC+LP+DP+EP | 0 | 0 | 0 | 0 | 0 | 0 | 1
- SP | A | 0 | 0 | 0 | 0 | 0 | 0 | 0 | A13
- A | 1 | 0 | 0 | 0 | 0 | 0 | 0 | A00
- A | 1 | 1 | 0 | 0 | 0 | 0 | 0 | A01
- A | 1 | 1 | 1 | 0 | 0 | 0 | 0 | A02
- A | 1 | 1 | 1 | 1 | 0 | 0 | 0 | A03
- A | 1 | 1 | 1 | 1 | 1 | 0 | 0 | A04
- A | 1 | 1 | 1 | 1 | 1 | 1 | 0 | A05
- A | 1 | 1 | 1 | 1 | 1 | 1 | 1 | A06
- A | 0 | 1 | 1 | 1 | 1 | 1 | 1 | A07
- A | 0 | 0 | 1 | 1 | 1 | 1 | 1 | A08
- A | 0 | 0 | 0 | 1 | 1 | 1 | 1 | A09
- A | 0 | 0 | 0 | 0 | 1 | 1 | 1 | A10
- A | 0 | 0 | 0 | 0 | 0 | 1 | 1 | A11
- A | 0 | 0 | 0 | 0 | 0 | 0 | 1 | A12
- Bit Timing
- D-BS-8S-0-11

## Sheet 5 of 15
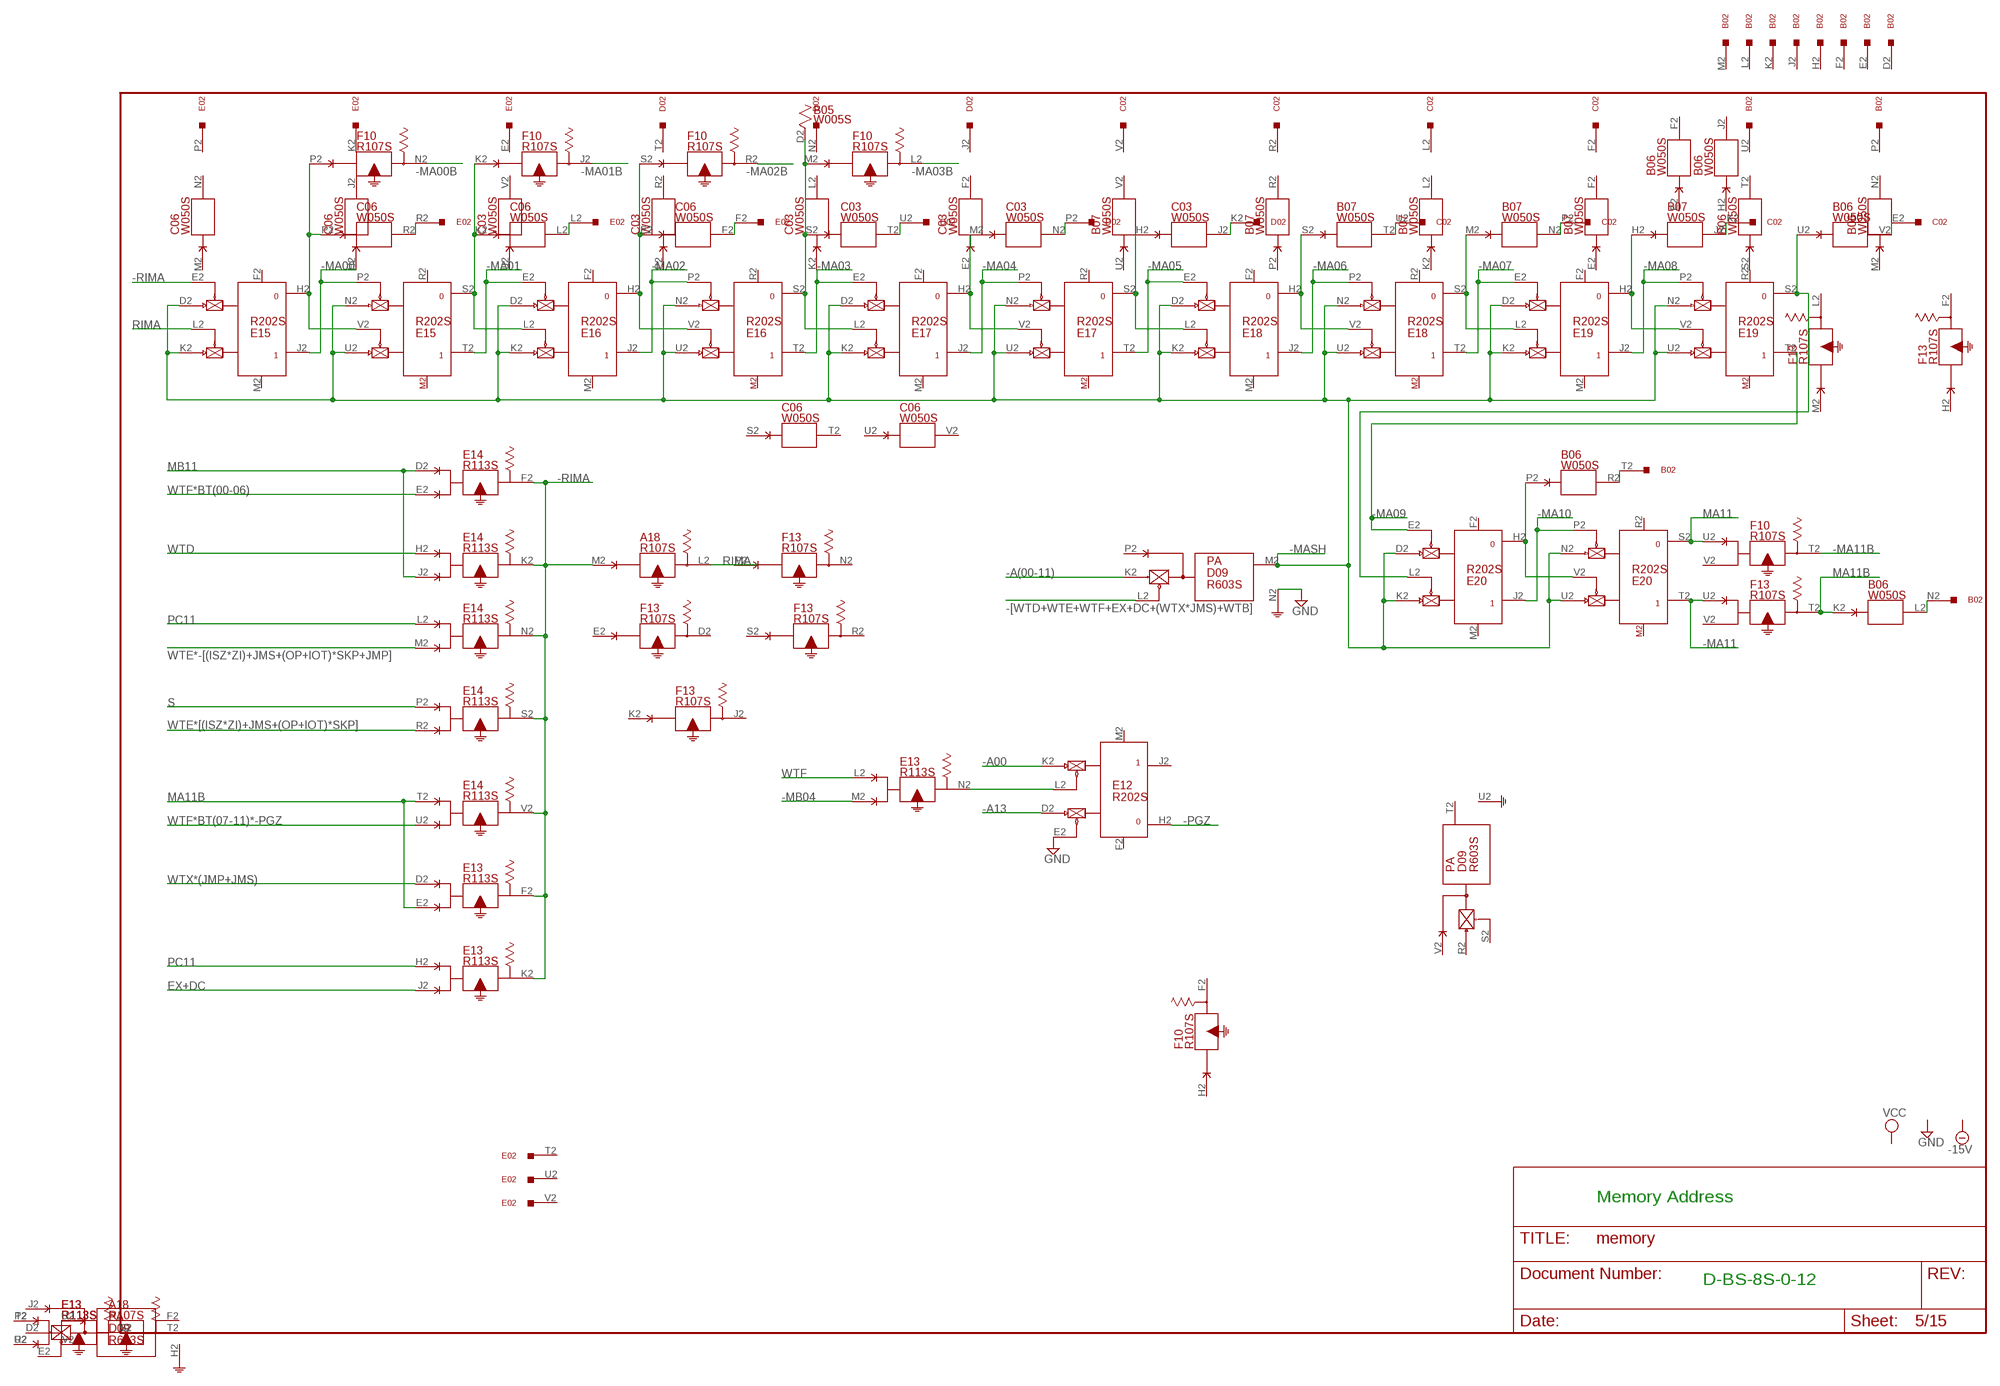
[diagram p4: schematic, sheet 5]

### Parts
A18  R107S  [H807S]
B05  W005S  [H807S]
E12  R202S  [H807S]
E13  R113S  [H807S]
E14  R113S  [H807S]
E15  R202S  [H807S]
E16  R202S  [H807S]
E17  R202S  [H807S]
E18  R202S  [H807S]
E19  R202S  [H807S]
E20  R202S  [H807S]

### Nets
-[WTD+WTE+WTF+EX+DC+(WTX*JMS)+WTB]: D09.L2(M:EN0) ; also sheet 6
-A00: E12.K2(J:PU1) ; also sheet 3,4,9,10,14,15
-A13: E12.D2(J:PU0) ; also sheet 1,4,6,7,10,15
-A(00-11): D09.K2(M:PU0) ; also sheet 1,3,4,7,9,11,12
-MA00: E15.J2 E15.P2(T:EN0) ; also sheet 2,15
-MA00B: F10.N2(N:O$1) ; also sheet 6
-MA01: E15.T2 E16.E2(J:EN0) ; also sheet 2,15
-MA01B: F10.J2(J:O$1) ; also sheet 6
-MA02: E16.J2 E16.P2(T:EN0) ; also sheet 2,15
-MA02B: F10.R2(R:O$1) ; also sheet 6
-MA03: E16.T2 E17.E2(J:EN0) ; also sheet 2,15
-MA03B: F10.L2(L:O$1) ; also sheet 6
-MA04: E17.J2 E17.P2(T:EN0) ; also sheet 2,6,15
-MA05: E17.T2 E18.E2(J:EN0) ; also sheet 2,15
-MA06: E18.J2 E18.P2(T:EN0) ; also sheet 2,15
-MA07: E18.T2 E19.E2(J:EN0) ; also sheet 2,15
-MA08: E19.J2 E19.P2(T:EN0) ; also sheet 2,15
-MA09: E19.T2 E20.E2(J:EN0) ; also sheet 2,15
-MA10: E20.J2 E20.P2(T:EN0) ; also sheet 2,15
-MA11: E20.T2 F13.U2(T:I$1) ; also sheet 2,15
-MA11B: F10.T2(T:O$1)
-MASH: D09.M2(M:O) E15.D2(J:PU0) E15.K2(J:PU1) E15.N2(T:PU0) E15.U2(T:PU1) E16.D2(J:PU0) E16.K2(J:PU1) E16.N2(T:PU0) E16.U2(T:PU1) E17.D2(J:PU0) E17.K2(J:PU1) E17.N2(T:PU0) E17.U2(T:PU1) E18.D2(J:PU0) E18.K2(J:PU1) E18.N2(T:PU0) E18.U2(T:PU1) E19.D2(J:PU0) E19.K2(J:PU1) E19.N2(T:PU0) E19.U2(T:PU1) E20.D2(J:PU0) E20.K2(J:PU1) E20.N2(T:PU0) E20.U2(T:PU1)
-MB04: E13.M2(N:I$2) ; also sheet 1,2,10
-PGZ: E12.H2 ; also sheet 6
-RIMA: A18.M2(L:I$1) E13.F2(F:O$1) E13.K2(K:O$1) E14.F2(F:O$1) E14.K2(K:O$1) E14.N2(N:O$1) E14.S2(S:O$1) E14.V2(V:O$1) E15.E2(J:EN0)
EX+DC: E13.J2(K:I$2) ; also sheet 7,8,9,12
GND [Supply]: D09.N2(M:G) E12.E2(J:EN0) ; also sheet 1,2,3,4,6,7,8,9,10,11,12,14,15
MA11: E20.S2 F10.U2(T:I$1)
MA11B: B06.K2(L:I$1) E13.E2(F:I$2) E14.T2(V:I$1) F13.T2(T:O$1) ; also sheet 11
MB11: E14.D2(F:I$1) E14.J2(K:I$2) ; also sheet 1,6,7,9,12
N$81: C06.P2(R:I$1) E15.H2 E15.V2(T:EN1) F10.P2(N:I$1)
N$82: E12.L2(J:EN1) E13.N2(N:O$1)
N$83: C06.K2(L:I$1) E15.S2 E16.L2(J:EN1) F10.K2(J:I$1)
N$84: C06.E2(F:I$1) E16.H2 E16.V2(T:EN1) F10.S2(R:I$1)
N$86: B05.D2 C03.S2(T:I$1) E16.S2 E17.L2(J:EN1) F10.M2(L:I$1)
N$87: C03.M2(N:I$1) E17.H2 E17.V2(T:EN1)
N$89: C03.H2(J:I$1) E17.S2 E18.L2(J:EN1)
N$90: B07.S2(T:I$1) E18.H2 E18.V2(T:EN1)
N$95: C06.R2(R:O$1) E02.R2
N$97: C06.L2(L:O$1) E02.L2
N$100: C06.F2(F:O$1) E02.F2
N$102: B07.M2(N:I$1) E18.S2 E19.L2(J:EN1)
N$104: C03.T2(T:O$1) D02.U2
N$106: B07.H2(J:I$1) E19.H2 E19.V2(T:EN1)
N$107: B06.U2(V:I$1) E19.S2 E20.L2(J:EN1)
N$109: C03.N2(N:O$1) D02.P2
N$110: B06.P2(R:I$1) E20.H2 E20.V2(T:EN1)
N$112: C03.J2(J:O$1) D02.K2
N$113: B07.T2(T:O$1) C02.U2
N$114: B07.N2(N:O$1) C02.P2
N$115: B07.J2(J:O$1) C02.K2
N$116: B06.V2(V:O$1) C02.E2
N$117: B02.T2 B06.R2(R:O$1)
N$118: B02.N2 B06.L2(L:O$1)
PC11: E13.H2(K:I$1) E14.L2(N:I$1) ; also sheet 1,7,11
RIMA: A18.L2(L:O$1) E15.L2(J:EN1)
S: E14.P2(S:I$1) ; also sheet 1,7,11,12
WTD: E14.H2(K:I$1) ; also sheet 6
WTE*-[(ISZ*ZI)+JMS+(OP+IOT)*SKP+JMP]: E14.M2(N:I$2) ; also sheet 6,11
WTE*[(ISZ*ZI)+JMS+(OP+IOT)*SKP]: E14.R2(S:I$2) ; also sheet 6,11
WTF: E13.L2(N:I$1) ; also sheet 1,3,6,8,10,12
WTF*BT(00-06): E14.E2(F:I$2) ; also sheet 6
WTF*BT(07-11)*-PGZ: E14.U2(V:I$2) ; also sheet 6
WTX*(JMP+JMS): E13.D2(F:I$1) ; also sheet 6,11,15
Unconnected: B05.E2 B05.F2 D09.J2(F:I$1) D09.P2(M:I$1) D09.V2(T:I$1) E15.F2(J:RESET) E15.M2(J:SET) E15.R2(T:RESET) E16.F2(J:RESET) E16.M2(J:SET) E16.R2(T:RESET) E17.F2(J:RESET) E17.M2(J:SET) E17.R2(T:RESET) E18.F2(J:RESET) E18.M2(J:SET) E18.R2(T:RESET) E19.F2(J:RESET) E19.M2(J:SET) E19.R2(T:RESET) E20.F2(J:RESET) E20.M2(J:SET) E20.R2(T:RESET)

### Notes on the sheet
- Memory Address
- D-BS-8S-0-12

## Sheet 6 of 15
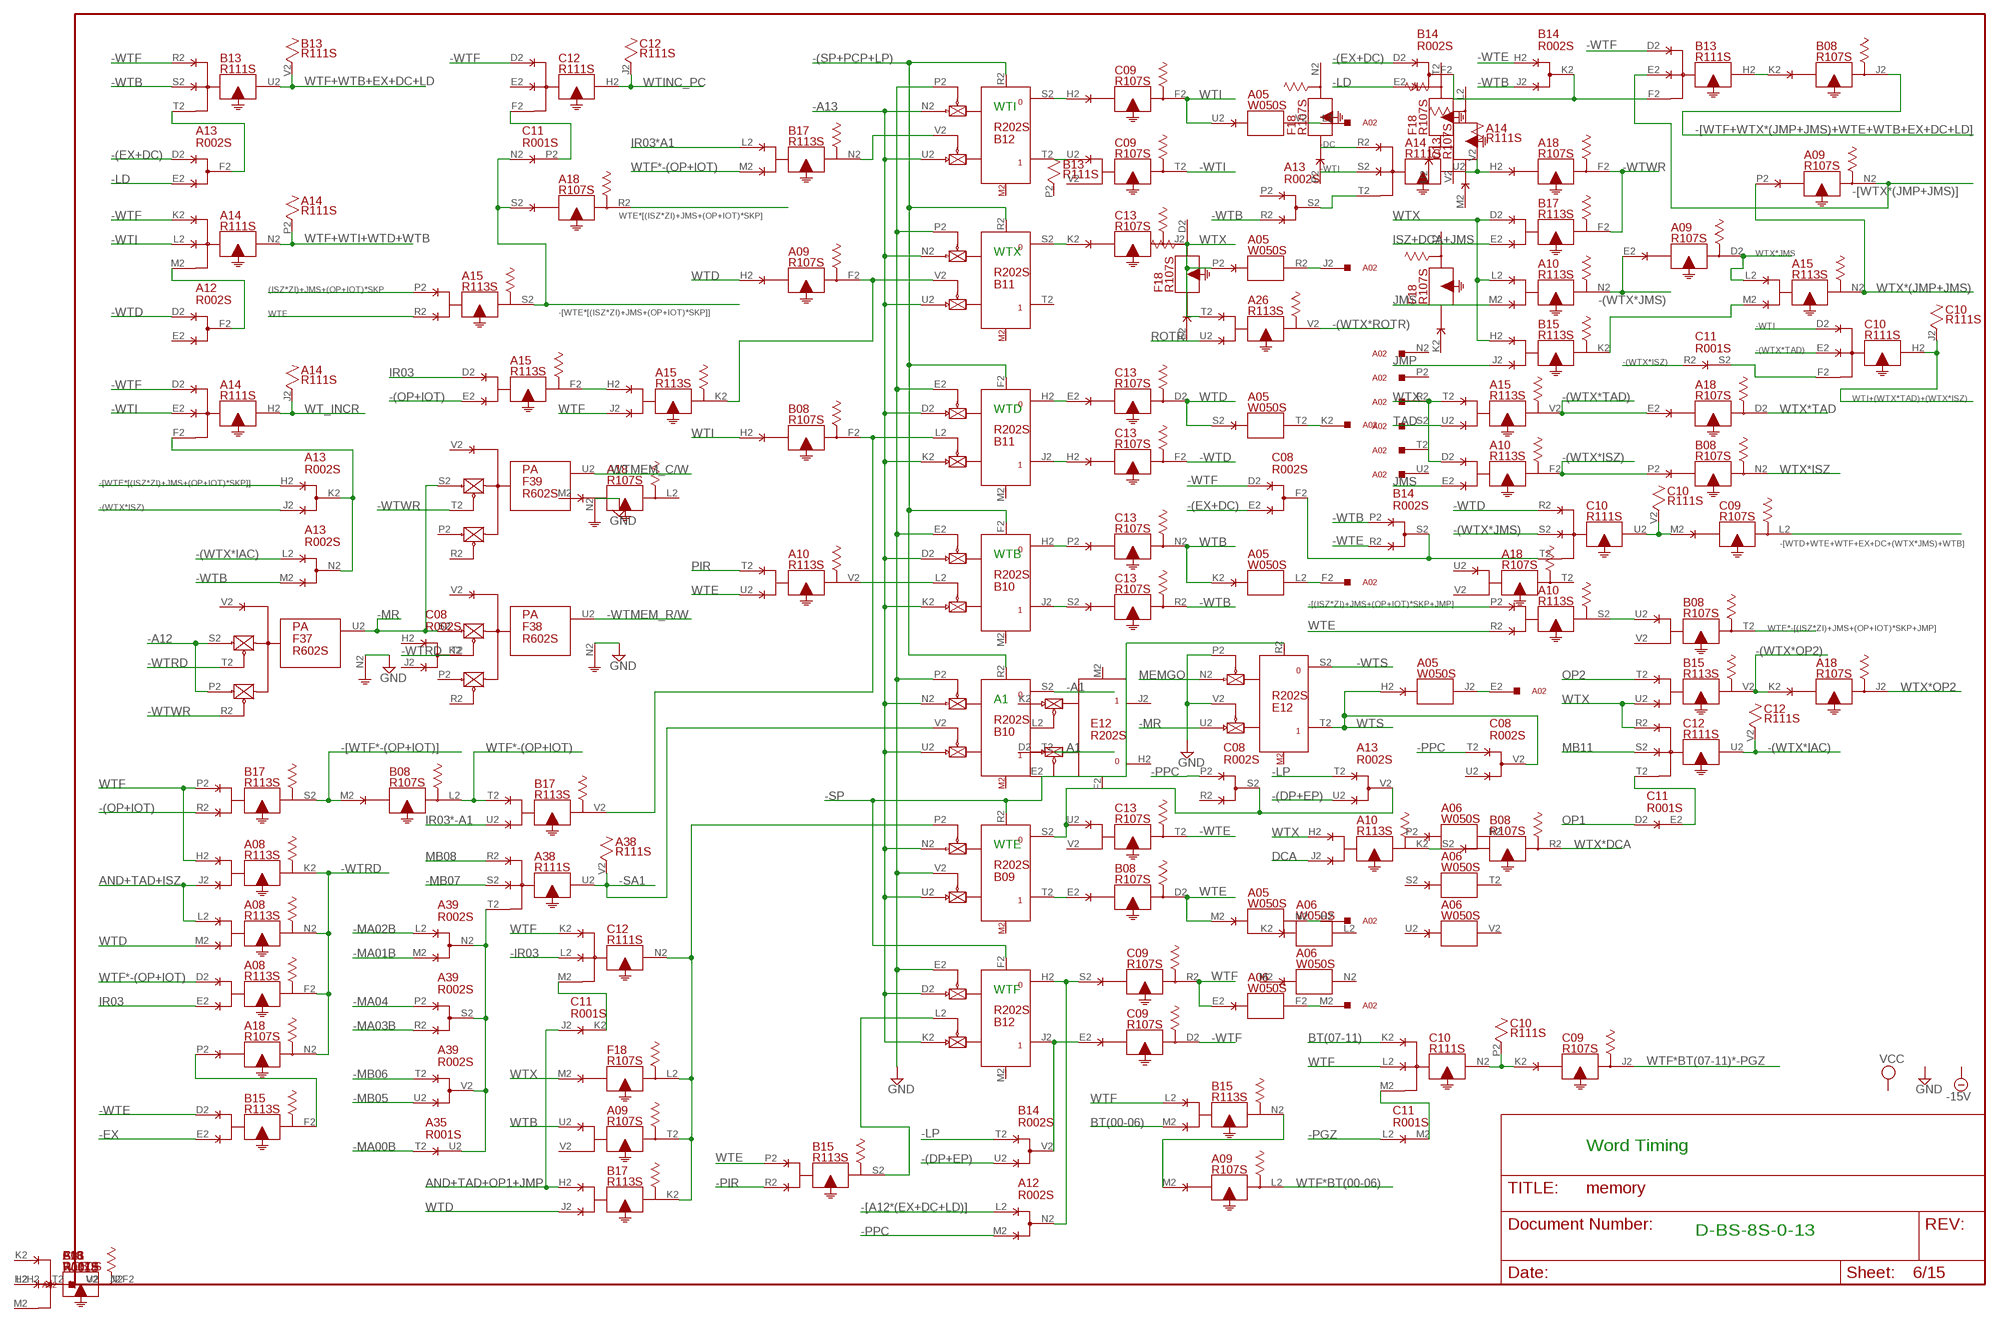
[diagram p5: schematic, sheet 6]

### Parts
A02  W023S  [H807S]
A05  W050S  [H807S]
A06  W050S  [H807S]
A08  R113S  [H807S]
A09  R107S  [H807S]
A10  R113S  [H807S]
A12  R002S  [H807S]
A13  R002S  [H807S]
A14  R111S  [H807S]
A15  R113S  [H807S]
A35  R001S  [H807S]
A38  R111S  [H807S]
A39  R002S  [H807S]
B08  R107S  [H807S]
B09  R202S  [H807S]
B10  R202S  [H807S]
B11  R202S  [H807S]
B12  R202S  [H807S]
B13  R111S  [H807S]
B14  R002S  [H807S]
B15  R113S  [H807S]
B17  R113S  [H807S]
C10  R111S  [H807S]
C11  R001S  [H807S]
C12  R111S  [H807S]
F37  R602S  [H807S]
F38  R602S  [H807S]
F39  R602S  [H807S]

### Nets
(ISZ*ZI)+JMS+(OP+IOT)*SKP: A15.P2(S:I$1) ; also sheet 9
-(DP+EP): A13.U2(V:E) B14.U2(V:E) ; also sheet 4,8,12
-(EX+DC): A13.D2(F:D) B14.D2(F:D) C08.E2(F:E) ; also sheet 8
-(OP+IOT): A15.E2(F:I$2) B17.R2(S:I$2) ; also sheet 1,9
-(SP+PCP+LP): B10.F2(J:RESET) B10.R2(T:RESET) B11.F2(J:RESET) B11.R2(T:RESET) B12.R2(T:RESET) ; also sheet 8,9
-(WTX*IAC): A13.L2(N:D) C12.U2(U:O$1) C12.V2
-(WTX*ISZ): A10.F2(F:O$1) A13.J2(K:E) B08.P2(N:I$1) C11.R2(S:D) ; also sheet 7
-(WTX*JMS): A09.E2(D:I$1) A10.N2(N:O$1) C10.S2(U:I$2)
-(WTX*OP2): A18.K2(J:I$1) B15.V2(V:O$1) ; also sheet 3,7
-(WTX*ROTR): A26.V2(V:O$1) ; also sheet 3,12
-(WTX*TAD): A15.V2(V:O$1) A18.E2(D:I$1) C10.E2(H:I$2) ; also sheet 12
-[(ISZ*ZI)+JMS+(OP+IOT)*SKP+JMP]: A10.P2(S:I$1) ; also sheet 9
-[A12*(EX+DC+LD)]: A12.L2(N:D) ; also sheet 8
-[WTD+WTE+WTF+EX+DC+(WTX*JMS)+WTB]: C09.L2(L:O$1) ; also sheet 5
-[WTE*[(ISZ*ZI)+JMS+(OP+IOT)*SKP]]: A13.H2(K:D) A15.S2(S:O$1) A18.S2(R:I$1) C11.N2(P:D)
-[WTF*-(OP+IOT)]: B08.M2(L:I$1) B17.S2(S:O$1)
-[WTF+WTX*(JMP+JMS)+WTE+WTB+EX+DC+LD]: B08.J2(J:O$1) ; also sheet 11
-[WTX*(JMP+JMS)]: A09.N2(N:O$1) B13.E2(H:I$2) ; also sheet 14
-A1: B10.S2 ; also sheet 9
-A12: F37.P2(U:E) F37.S2(U:H) ; also sheet 1,3,4,8,10,12,15
-A13: B09.N2(T:PU0) B09.U2(T:PU1) B10.D2(J:PU0) B10.K2(J:PU1) B10.N2(T:PU0) B10.U2(T:PU1) B11.D2(J:PU0) B11.K2(J:PU1) B11.N2(T:PU0) B11.U2(T:PU1) B12.D2(J:PU0) B12.K2(J:PU1) B12.N2(T:PU0) B12.U2(T:PU1) ; also sheet 1,4,5,7,10,15
-DC: A14.R2(U:I$1) ; also sheet 8
-EX: B15.E2(F:I$2) ; also sheet 8
-IR03: C12.L2(N:I$2) ; also sheet 9
-LD: A13.E2(F:E) B14.E2(F:E) ; also sheet 8,15
-LP: A13.T2(V:D) B14.T2(V:D) ; also sheet 4,8,12,15
-MA00B: A35.T2(U:D) ; also sheet 5
-MA01B: A39.M2(N:E) ; also sheet 5
-MA02B: A39.L2(N:D) ; also sheet 5
-MA03B: A39.R2(S:E) ; also sheet 5
-MA04: A39.P2(S:D) ; also sheet 2,5,15
-MB05: A39.U2(V:E) ; also sheet 1,2,10
-MB06: A39.T2(V:D) ; also sheet 1,2,7,10
-MB07: A38.S2(U:I$2) ; also sheet 1,2,10
-MR: E12.U2(T:PU1) F37.U2(U:K) F38.S2(U:H) F39.S2(U:H)
-PGZ: C11.L2(M:D) ; also sheet 5
-PIR: B15.R2(S:I$2) ; also sheet 10
-PPC: A12.M2(N:E) C08.P2(S:D) C08.T2(V:D) ; also sheet 4,8,10,11,15
-SA1: A38.U2(U:O$1) A38.V2 B10.V2(T:EN1)
-SP: B09.R2(T:RESET) B12.F2(J:RESET) E12.R2(T:RESET) ; also sheet 1,8
-WTB: A13.M2(N:E) A13.R2(S:E) B13.S2(U:I$2) B14.J2(K:E) B14.P2(S:D) C13.R2(R:O$1) ; also sheet 9,15
-WTD: A12.D2(F:D) C10.R2(U:I$1) C13.F2(F:O$1) ; also sheet 15
-WTE: B14.H2(K:D) B14.R2(S:E) B15.D2(F:I$1) C13.T2(T:O$1) ; also sheet 3
-WTF: A14.D2(H:I$1) A14.K2(N:I$1) B13.D2(H:I$1) B13.R2(U:I$1) C08.D2(F:D) C09.D2(D:O$1) C12.D2(H:I$1) ; also sheet 7,9,15
-WTI: A14.E2(H:I$2) A14.L2(N:I$2) A14.S2(U:I$2) C09.T2(T:O$1) C10.D2(H:I$1)
-WTMEM_C/W: F39.U2(U:K) ; also sheet 13
-WTMEM_R/W: F38.U2(U:K) ; also sheet 1,13
-WTRD: A08.F2(F:O$1) A08.K2(K:O$1) A08.N2(N:O$1) A18.N2(N:O$1) F37.T2(U:J) F38.T2(U:J)
-WTS: E12.S2 ; also sheet 1,4
-WTWR: A18.F2(F:O$1) B17.F2(F:O$1) F37.R2(U:F) F39.T2(U:J) ; also sheet 1
A1: B10.T2 ; also sheet 9
AND+TAD+ISZ: A08.J2(K:I$2) A08.L2(N:I$1) ; also sheet 1,9
AND+TAD+OP1+JMP: B17.H2(K:I$1) C11.J2(K:D) ; also sheet 9
BT(00-06): B15.M2(N:I$2) ; also sheet 4
BT(07-11): C10.K2(N:I$1) ; also sheet 4
DCA: A10.J2(K:I$2) ; also sheet 9
GND [Supply]: B09.V2(T:EN1) B10.E2(J:EN0) B10.P2(T:EN0) B11.E2(J:EN0) B11.P2(T:EN0) B12.E2(J:EN0) B12.P2(T:EN0) E12.P2(T:EN0) E12.V2(T:EN1) F37.N2(U:C) F38.N2(U:C) F39.N2(U:C) ; also sheet 1,2,3,4,5,7,8,9,10,11,12,14,15
IR03: A08.E2(F:I$2) A15.D2(F:I$1) ; also sheet 9
IR03*-A1: B17.U2(V:I$2) ; also sheet 9
IR03*A1: B17.L2(N:I$1) ; also sheet 9
ISZ+DCA+JMS: B17.E2(F:I$2) ; also sheet 9
JMP: B15.J2(K:I$2) ; also sheet 9
JMS: A10.E2(F:I$2) A10.M2(N:I$2) ; also sheet 9
MB08: A38.R2(U:I$1) ; also sheet 1,3,9
MB11: C12.S2(U:I$2) ; also sheet 1,5,7,9,12
MEMGO: E12.N2(T:PU0) ; also sheet 13
N$92: A13.F2(F:F) B13.T2(U:I$3)
N$120: C11.P2(P:E) C12.F2(H:I$3)
N$121: A13.K2(K:F) A13.N2(N:F) A14.F2(H:I$3)
N$122: A15.F2(F:O$1) A15.H2(K:I$1)
N$125: A12.F2(F:F) A14.M2(N:I$3)
N$126: A35.U2(U:E) A38.T2(U:I$3) A39.N2(N:F) A39.S2(S:F) A39.V2(V:F)
N$127: C11.K2(K:E) C12.M2(N:I$3)
N$128: A18.P2(N:I$1) B15.F2(F:O$1)
N$129: B12.S2 C09.H2(F:I$1)
N$130: B12.T2 C09.U2(T:I$1)
N$131: B11.S2 C13.K2(J:I$1)
N$132: B11.H2 C13.E2(D:I$1)
N$133: B11.J2 C13.H2(F:I$1)
N$134: B10.H2 C13.P2(N:I$1)
N$135: B10.J2 C13.S2(R:I$1)
N$136: B12.J2 B14.V2(V:F) C09.E2(D:I$1)
N$137: A09.T2(T:O$1) B09.P2(T:EN0) B17.K2(K:O$1) C12.N2(N:O$1) F18.L2(L:O$1)
N$138: A10.V2(V:O$1) B10.L2(J:EN1)
N$139: B08.F2(F:O$1) B11.L2(J:EN1) B17.V2(V:O$1)
N$140: A09.F2(F:O$1) A15.K2(K:O$1) B11.V2(T:EN1)
N$141: B12.V2(T:EN1) B17.N2(N:O$1)
N$142: B08.E2(D:I$1) B09.T2
N$143: A13.V2(V:F) B09.S2 C08.S2(S:F) C13.U2(T:I$1)
N$144: A12.N2(N:F) B12.H2 C09.S2(R:I$1)
N$145: A02.M2 A06.F2(F:O$1)
N$146: A02.H2 A05.N2(N:O$1)
N$147: A02.F2 A05.L2(L:O$1)
N$148: B12.L2(J:EN1) B15.S2(S:O$1)
N$149: A02.L2 A05.V2(V:O$1)
N$150: A02.J2 A05.R2(R:O$1)
N$151: A02.K2 A05.T2(T:O$1)
N$152: A14.U2(U:O$1) A14.V2 A18.H2(F:I$1)
N$153: A15.M2(N:I$2) B15.K2(K:O$1)
N$154: A13.S2(S:F) A14.T2(U:I$3)
N$155: B08.K2(J:I$1) B13.H2(H:O$1)
N$156: B13.F2(H:I$3) B14.F2(F:F) B14.K2(K:F)
N$157: B14.S2(S:F) C08.F2(F:F) C10.T2(U:I$3)
N$158: C09.M2(L:I$1) C10.U2(U:O$1) C10.V2
N$159: C10.F2(H:I$3) C11.S2(S:E)
N$160: A02.E2 A05.J2(J:O$1)
N$161: A10.S2(S:O$1) B08.U2(T:I$1)
N$162: A09.M2(L:I$1) B15.N2(N:O$1)
N$163: C10.M2(N:I$3) C11.M2(M:E)
N$164: C09.K2(J:I$1) C10.N2(N:O$1) C10.P2
N$166: A10.K2(K:O$1) B08.S2(R:I$1)
N$168: C11.E2(E:E) C12.T2(U:I$3)
OP1: C11.D2(E:D) ; also sheet 7,9,12
OP2: B15.T2(V:I$1) ; also sheet 3,7,8,9,12
PIR: A10.T2(V:I$1) ; also sheet 10
ROTR: A26.U2(V:I$2) ; also sheet 9
TAD: A15.U2(V:I$2) ; also sheet 9
WT_INCR: A14.H2(H:O$1) A14.J2 ; also sheet 7
WTB: A05.K2(L:I$1) A09.U2(T:I$1) C13.N2(N:O$1) ; also sheet 1
WTD: A05.S2(T:I$1) A08.M2(N:I$2) A09.H2(F:I$1) B17.J2(K:I$2) C13.D2(D:O$1) ; also sheet 5
WTE: A05.M2(N:I$1) A10.R2(S:I$2) A10.U2(V:I$2) A15.R2(S:I$2) B08.D2(D:O$1) B15.P2(S:I$1) ; also sheet 1,3,8
WTE*-[(ISZ*ZI)+JMS+(OP+IOT)*SKP+JMP]: B08.T2(T:O$1) ; also sheet 5,11
WTE*[(ISZ*ZI)+JMS+(OP+IOT)*SKP]: A18.R2(R:O$1) ; also sheet 5,11
WTF: A06.E2(F:I$1) A08.H2(K:I$1) A15.J2(K:I$2) B15.L2(N:I$1) B17.P2(S:I$1) C09.R2(R:O$1) C10.L2(N:I$2) C12.K2(N:I$1) ; also sheet 1,3,5,8,10,12
WTF*-(OP+IOT): A08.D2(F:I$1) B08.L2(L:O$1) B17.M2(N:I$2) B17.T2(V:I$1)
WTF*BT(00-06): A09.L2(L:O$1) ; also sheet 5
WTF*BT(07-11)*-PGZ: C09.J2(J:O$1) ; also sheet 5
WTF+WTB+EX+DC+LD: B13.U2(U:O$1) B13.V2 ; also sheet 11
WTF+WTI+WTD+WTB: A14.N2(N:O$1) A14.P2 ; also sheet 1
WTI: A05.U2(V:I$1) B08.H2(F:I$1) C09.F2(F:O$1) ; also sheet 1
WTI+(WTX*TAD)+(WTX*ISZ): C10.H2(H:O$1) C10.J2 ; also sheet 7
WTINC_PC: C12.H2(H:O$1) C12.J2 ; also sheet 7
WTS: A05.H2(J:I$1) C08.V2(V:F) E12.T2 ; also sheet 8
WTX: A05.P2(R:I$1) A10.D2(F:I$1) A10.H2(K:I$1) A10.L2(N:I$1) A15.T2(V:I$1) A26.T2(V:I$1) B15.H2(K:I$1) B15.U2(V:I$2) B17.D2(F:I$1) C12.R2(U:I$1) C13.J2(J:O$1) F18.M2(L:I$1) ; also sheet 1,3,7,10,12,15
WTX*(JMP+JMS): A09.P2(N:I$1) A15.N2(N:O$1) ; also sheet 5,11,15
WTX*DCA: B08.R2(R:O$1) ; also sheet 1
WTX*ISZ: B08.N2(N:O$1) ; also sheet 1
WTX*JMS: A09.D2(D:O$1) A15.L2(N:I$1) ; also sheet 1
WTX*OP2: A18.J2(J:O$1) ; also sheet 12
WTX*TAD: A18.D2(D:O$1) ; also sheet 7
Unconnected: A02.A2 A02.B2 A02.C2 A09.V2(T:I$2) A12.E2(F:E) A12.H2(K:D) A12.J2(K:E) A12.K2(K:F) A13.P2(S:D) B08.V2(T:I$2) B10.M2(J:SET) B11.M2(J:SET) B11.T2 B12.M2(J:SET) B13.J2 C08.R2(S:E) C08.U2(V:E) C09.V2(T:I$2) C12.E2(H:I$2) C12.P2 C13.V2(T:I$2) E12.F2(J:RESET) E12.J2 E12.M2(J:SET) F37.V2(U:L) F38.P2(U:E) F38.R2(U:F) F38.V2(U:L) F39.P2(U:E) F39.R2(U:F) F39.V2(U:L)

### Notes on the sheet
- WTI
- WTX
- WTD
- WTB
- A1
- WTE
- WTF
- Word Timing
- D-BS-8S-0-13

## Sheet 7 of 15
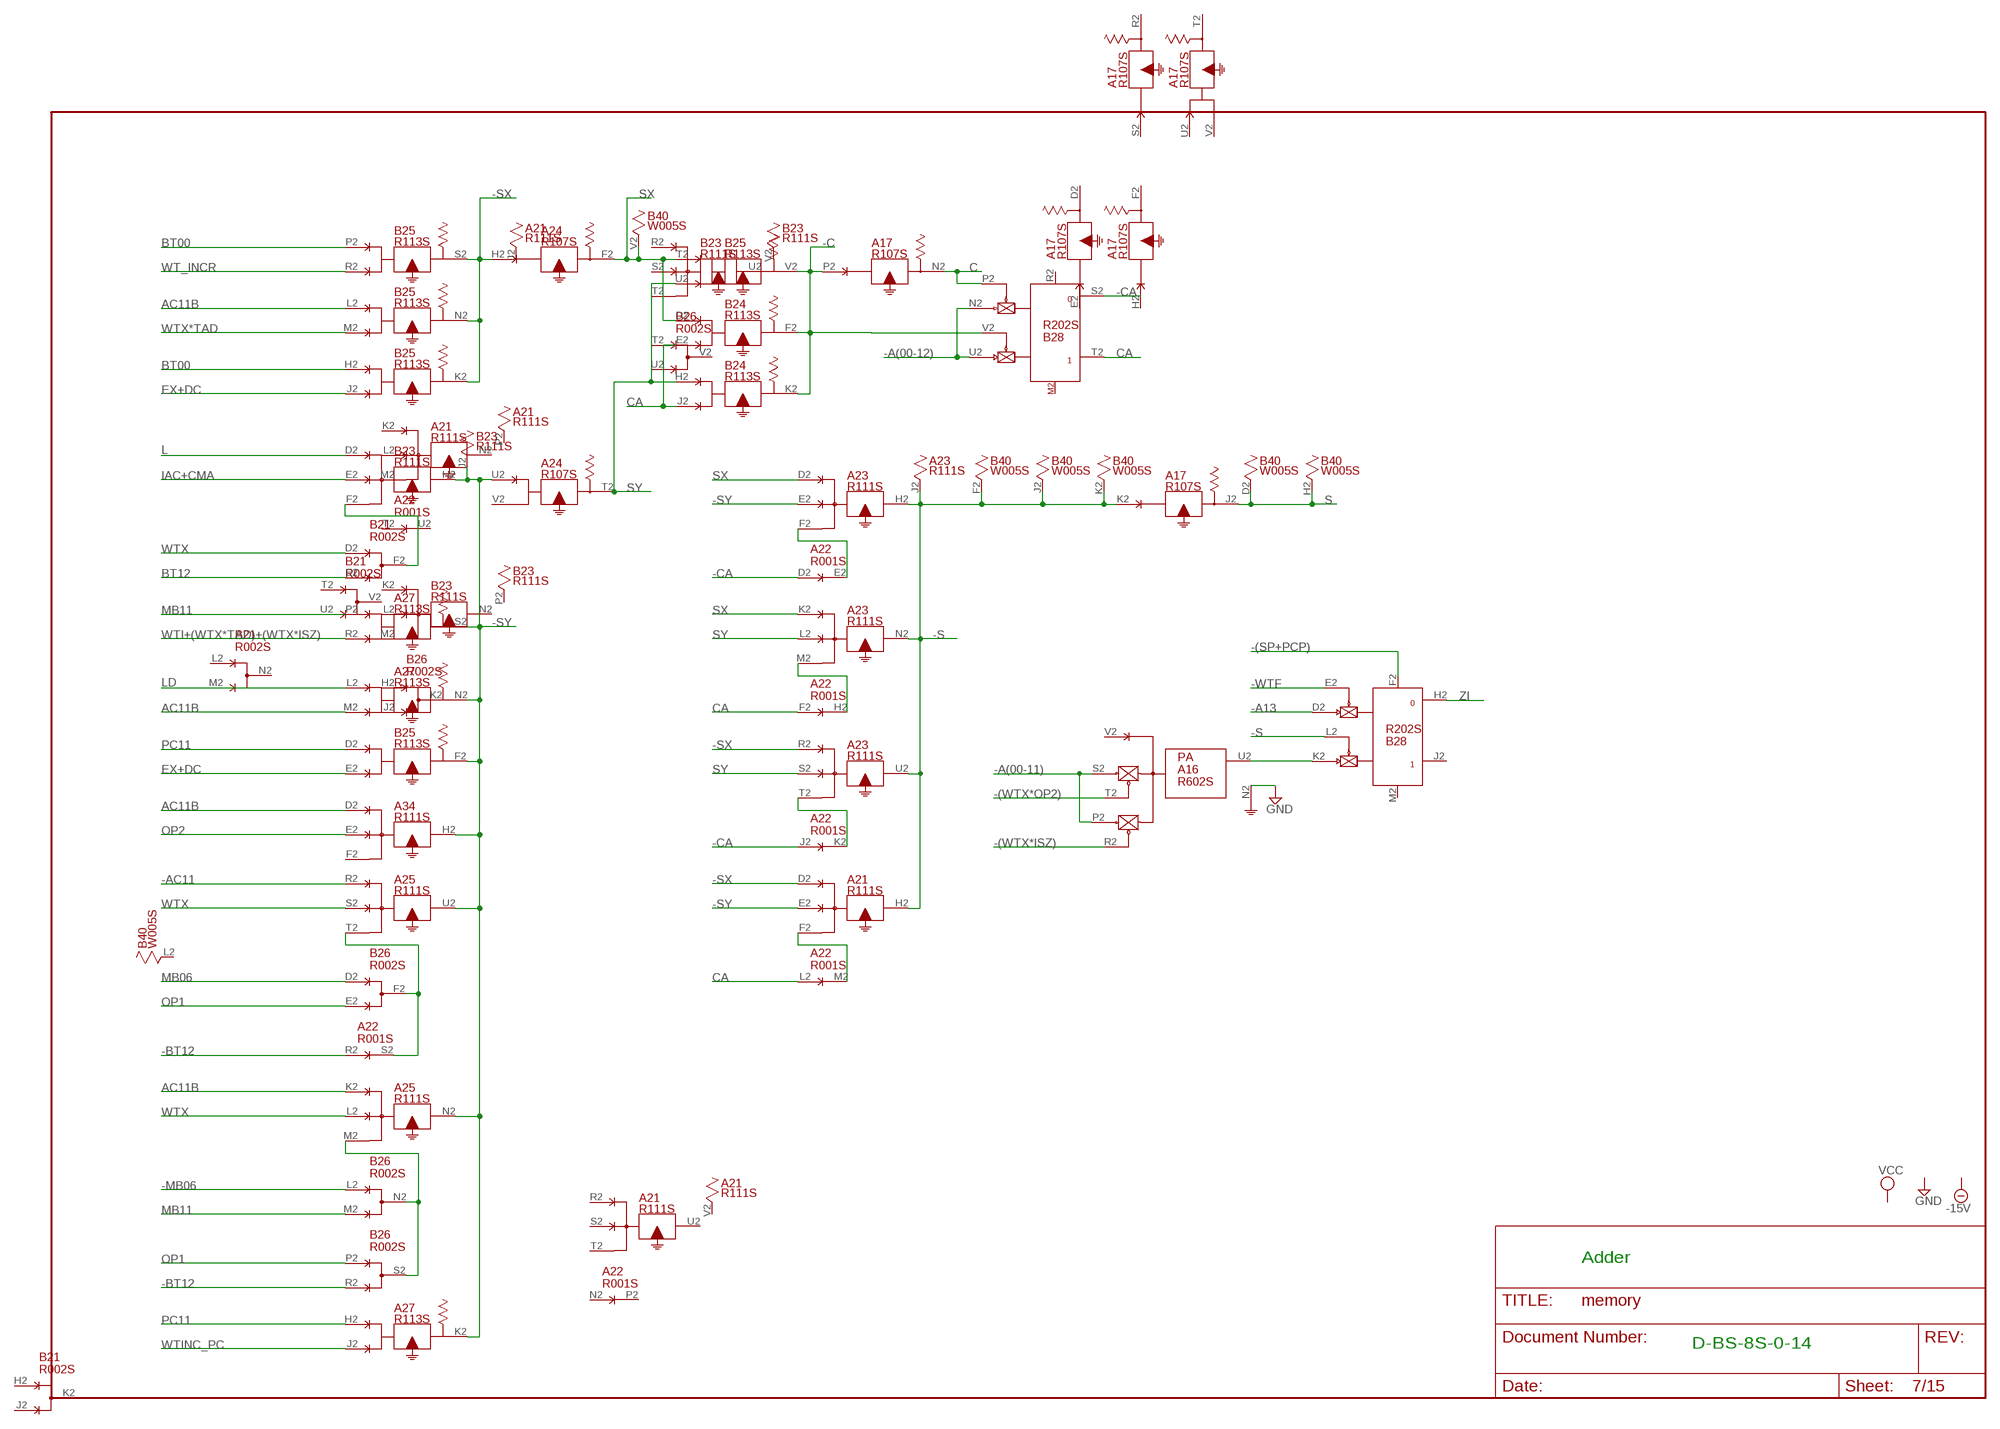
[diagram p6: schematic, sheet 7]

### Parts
A16  R602S  [H807S]
A23  R111S  [H807S]
A25  R111S  [H807S]
A34  R111S  [H807S]
B21  R002S  [H807S]
B24  R113S  [H807S]
B25  R113S  [H807S]
B28  R202S  [H807S]

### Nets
-(SP+PCP): B28.F2(J:RESET) ; also sheet 1,3,8,10,12,14,15
-(WTX*ISZ): A16.R2(U:F) ; also sheet 6
-(WTX*OP2): A16.T2(U:J) ; also sheet 3,6
-A13: B28.D2(J:PU0) ; also sheet 1,4,5,6,10,15
-A(00-11): A16.P2(U:E) A16.S2(U:H) ; also sheet 1,3,4,5,9,11,12
-A(00-12): B28.N2(T:PU0) B28.U2(T:PU1) ; also sheet 4
-AC11: A25.R2(U:I$1) ; also sheet 12
-BT12: A22.R2(S:D) B26.R2(S:E) ; also sheet 4
-C: A17.P2(N:I$1) B24.F2(F:O$1) B24.K2(K:O$1) B25.V2(V:O$1) B28.V2(T:EN1)
-CA: A22.D2(E:D) A22.J2(K:D) B28.S2
-MB06: B26.L2(N:D) ; also sheet 1,2,6,10
-S: A17.K2(J:I$1) A21.H2(H:O$1) A23.H2(H:O$1) A23.J2 A23.N2(N:O$1) A23.U2(U:O$1) B28.L2(J:EN1) B40.F2 B40.J2 B40.K2
-SX: A21.D2(H:I$1) A23.R2(U:I$1) A24.H2(F:I$1) B25.K2(K:O$1) B25.N2(N:O$1) B25.S2(S:O$1)
-SY: A21.E2(H:I$2) A23.E2(H:I$2) A24.U2(T:I$1) A25.N2(N:O$1) A25.U2(U:O$1) A27.K2(K:O$1) A27.N2(N:O$1) A27.S2(S:O$1) A34.H2(H:O$1) B23.H2(H:O$1) B23.J2 B25.F2(F:O$1)
-WTF: B28.E2(J:EN0) ; also sheet 6,9,15
AC11B: A25.K2(N:I$1) A27.M2(N:I$2) A34.D2(H:I$1) B25.L2(N:I$1) ; also sheet 1,12
BT00: B25.H2(K:I$1) B25.P2(S:I$1) ; also sheet 4,9,15
BT12: B21.E2(F:E) ; also sheet 4
C: A17.N2(N:O$1) B28.P2(T:EN0)
CA: A22.F2(H:D) A22.L2(M:D) B24.E2(F:I$2) B24.J2(K:I$2) B28.T2
EX+DC: B25.E2(F:I$2) B25.J2(K:I$2) ; also sheet 5,8,9,12
GND [Supply]: A16.N2(U:C) ; also sheet 1,2,3,4,5,6,8,9,10,11,12,14,15
IAC+CMA: B23.E2(H:I$2) ; also sheet 9,12
L: B23.D2(H:I$1) ; also sheet 3,12
LD: A27.L2(N:I$1) ; also sheet 8,12
MB06: B26.D2(F:D) ; also sheet 1,3,9
MB11: A27.P2(S:I$1) B26.M2(N:E) ; also sheet 1,5,6,9,12
N$165: B21.F2(F:F) B23.F2(H:I$3)
N$167: A16.U2(U:K) B28.K2(J:PU1)
N$169: A22.S2(S:E) A25.T2(U:I$3) B26.F2(F:F)
N$170: A22.E2(E:E) A23.F2(H:I$3)
N$171: A25.M2(N:I$3) B26.N2(N:F) B26.S2(S:F)
N$172: A22.H2(H:E) A23.M2(N:I$3)
N$174: A22.K2(K:E) A23.T2(U:I$3)
N$175: A21.F2(H:I$3) A22.M2(M:E)
OP1: B26.E2(F:E) B26.P2(S:D) ; also sheet 6,9,12
OP2: A34.E2(H:I$2) ; also sheet 3,6,8,9,12
PC11: A27.H2(K:I$1) B25.D2(F:I$1) ; also sheet 1,5,11
S: A17.J2(J:O$1) B40.D2 B40.H2 ; also sheet 1,5,11,12
SX: A23.D2(H:I$1) A23.K2(N:I$1) A24.F2(F:O$1) B24.D2(F:I$1) B25.T2(V:I$1) B40.V2
SY: A23.L2(N:I$2) A23.S2(U:I$2) A24.T2(T:O$1) B24.H2(K:I$1) B25.U2(V:I$2)
WT_INCR: B25.R2(S:I$2) ; also sheet 6
WTI+(WTX*TAD)+(WTX*ISZ): A27.R2(S:I$2) ; also sheet 6
WTINC_PC: A27.J2(K:I$2) ; also sheet 6
WTX: A25.L2(N:I$2) A25.S2(U:I$2) B21.D2(F:D) ; also sheet 1,3,6,10,12,15
WTX*TAD: B25.M2(N:I$2) ; also sheet 6
ZI: B28.H2 ; also sheet 3,9
Unconnected: A23.P2 A23.V2 A25.P2 A25.V2 A34.J2 A34.V2 B26.U2(V:E) B28.J2 B28.M2(J:SET) B28.R2(T:RESET)

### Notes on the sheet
- Adder
- D-BS-8S-0-14

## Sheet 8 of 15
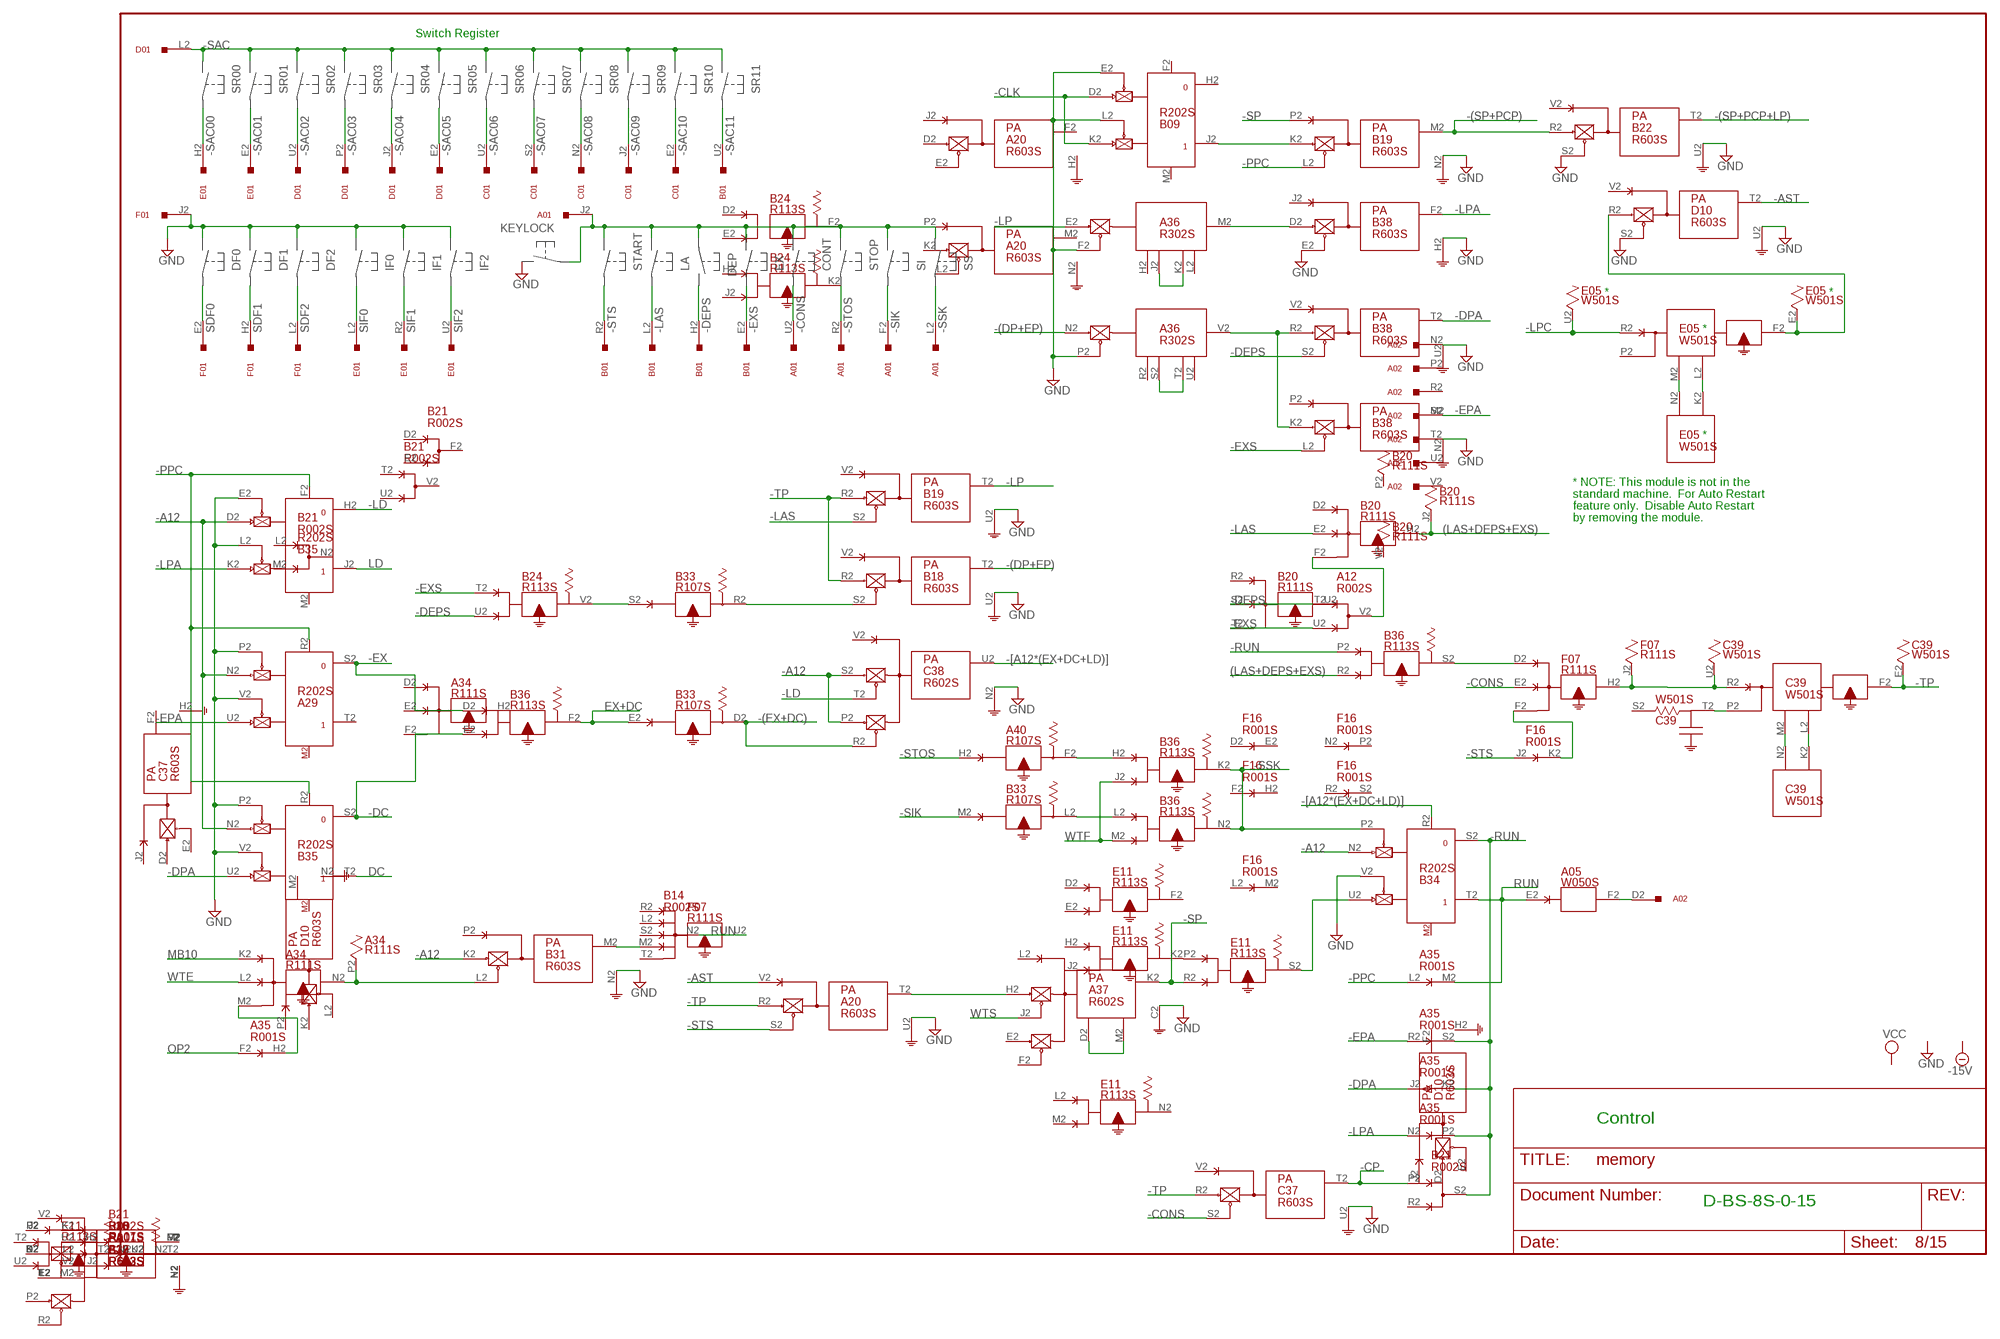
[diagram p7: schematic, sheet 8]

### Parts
A01  W023S  [H807S]
A36  R302S  [H807S]
A37  R602S  [H807S]
A40  R107S  [H807S]
B01  W023S  [H807S]
B18  R603S  [H807S]
B19  R603S  [H807S]
B20  R111S  [H807S]
B22  R603S  [H807S]
B34  R202S  [H807S]
B35  R202S  [H807S]
B36  R113S  [H807S]
B38  R603S  [H807S]
C01  W023S  [H807S]
C38  R602S  [H807S]
C39  W501S  [H807S]
D01  W023S  [H807S]
E01  W023S  [H807S]
E05  W501S  [H807S]
E11  R113S  [H807S]
F01  W023S  [H807S]
F16  R001S  [H807S]

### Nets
(LAS+DEPS+EXS): B20.H2(H:O$1) B20.J2 B36.R2(S:I$2)
-(DP+EP): A36.N2(V:E) B18.T2(T:O) ; also sheet 4,6,12
-(EX+DC): B33.D2(D:O$1) C38.R2(U:F) ; also sheet 6
-(SP+PCP): B19.M2(M:O) B22.R2(T:PU0) ; also sheet 1,3,7,10,12,14,15
-(SP+PCP+LP): B22.T2(T:O) ; also sheet 6,9
-[A12*(EX+DC+LD)]: B34.R2(T:RESET) C38.U2(U:K) ; also sheet 6
-A12: A29.N2(T:PU0) B31.K2(M:PU0) B34.N2(T:PU0) B35.D2(J:PU0) B35.N2(T:PU0) C38.P2(U:E) C38.S2(U:H) ; also sheet 1,3,4,6,10,12,15
-AST: A20.V2(T:I$1) D10.T2(T:O)
-CLK: B09.D2(J:PU0) B09.K2(J:PU1) ; also sheet 4,15
-CONS: A01.U2 C37.S2(T:EN0) F07.E2(H:I$2)
-CP: B21.P2(S:D) C37.T2(T:O)
-DC: B35.S2 B36.E2(F:I$2) ; also sheet 6
-DEPS: A12.T2(V:D) B01.H2 B24.U2(V:I$2) B38.S2(T:EN0)
-DPA: A35.J2(K:D) B35.U2(T:PU1) B38.T2(T:O) ; also sheet 3
-EPA: A29.U2(T:PU1) A35.R2(S:D) B38.M2(M:O) ; also sheet 1
-EX: A29.S2 B36.D2(F:I$1) ; also sheet 6
-EXS: A12.U2(V:E) B01.E2 B24.T2(V:I$1) B38.L2(M:EN0)
-LAS: B01.L2 B19.S2(T:EN0) B20.E2(H:I$2)
-LD: B35.H2 C38.T2(U:J) ; also sheet 6,15
-LP: A36.E2(M:E) B19.T2(T:O) ; also sheet 4,6,12,15
-LPA: A35.N2(P:D) B35.K2(J:PU1) B38.F2(F:O) ; also sheet 3
-LPC: E05.R2(F:R) E05.U2 ; also sheet 10
-PPC: A29.R2(T:RESET) A35.L2(M:D) B19.L2(M:EN0) B35.F2(J:RESET) B35.R2(T:RESET) ; also sheet 4,6,10,11,15
-RUN: A35.K2(K:E) A35.P2(P:E) A35.S2(S:E) B21.S2(S:F) B34.S2 B36.P2(S:I$1) ; also sheet 4,10
-SAC: D01.L2 ; also sheet 3
-SAC00: E01.H2 ; also sheet 12
-SAC01: E01.E2 ; also sheet 12
-SAC02: D01.U2 ; also sheet 12
-SAC03: D01.P2 ; also sheet 12
-SAC04: D01.J2 ; also sheet 12
-SAC05: D01.E2 ; also sheet 12
-SAC06: C01.U2 ; also sheet 12
-SAC07: C01.S2 ; also sheet 12
-SAC08: C01.N2 ; also sheet 12
-SAC09: C01.J2 ; also sheet 12
-SAC10: C01.E2 ; also sheet 12
-SAC11: B01.U2 ; also sheet 12
-SIK: A01.F2 B33.M2(L:I$1)
-SP: A37.K2(K:K) B19.P2(M:I$1) E11.R2(S:I$2) ; also sheet 1,6
-SSK: A01.L2 B34.P2(T:EN0) B36.K2(K:O$1) B36.N2(N:O$1)
-STOS: A01.R2 A40.H2(F:I$1)
-STS: A20.S2(T:EN0) B01.R2 F16.J2(K:D)
-TP: A20.R2(T:PU0) B18.R2(T:PU0) B19.R2(T:PU0) C37.R2(T:PU0) C39.E2 C39.F2(F:F)
DC: B35.T2 ; also sheet 1,12
EX+DC: B33.E2(D:I$1) B36.F2(F:O$1) ; also sheet 5,7,9,12
GND [Supply]: A20.U2(T:G) A29.P2(T:EN0) A29.V2(T:EN1) A36.F2(M:F) A36.P2(V:F) A37.C2(K:GND) B09.E2(J:EN0) B09.L2(J:EN1) B18.U2(T:G) B19.N2(M:G) B19.U2(T:G) B22.S2(T:EN0) B22.U2(T:G) B31.N2(M:G) B34.V2(T:EN1) B35.E2(J:EN0) B35.L2(J:EN1) B35.P2(T:EN0) B35.V2(T:EN1) B38.E2(F:EN0) B38.H2(F:G) B38.N2(M:G) B38.U2(T:G) C37.U2(T:G) C38.N2(U:C) D10.S2(T:EN0) D10.U2(T:G) F01.J2 ; also sheet 1,2,3,4,5,6,7,9,10,11,12,14,15
KEYLOCK: A01.J2
LD: B35.J2 ; also sheet 7,12
MB10: A34.K2(N:I$1) ; also sheet 1,9
N$177: A34.M2(N:I$3) A35.H2(H:E)
N$178: A34.N2(N:O$1) A34.P2 B31.L2(M:EN0)
N$179: B14.M2(N:E) B31.M2(M:O)
N$180: B24.V2(V:O$1) B33.S2(R:I$1)
N$181: B34.U2(T:PU1) E11.S2(S:O$1)
N$182: B18.S2(T:EN0) B33.R2(R:O$1)
N$183: A36.S2(V:J) A36.T2(V:K)
N$184: A36.J2(M:J) A36.K2(M:K)
N$185: E05.M2(F:M) E05.N2(K:N)
N$186: E05.K2(K:K) E05.L2(F:L)
N$187: B09.J2 B19.K2(M:PU0)
N$188: D10.R2(T:PU0) E05.E2 E05.F2(F:F)
N$189: A36.M2(M:M) B38.D2(F:PU0)
N$190: A36.V2(V:M) B38.K2(M:PU0) B38.R2(T:PU0)
N$191: A12.V2(V:F) B20.F2(H:I$3)
N$192: C39.M2(F:M) C39.N2(K:N)
N$193: C39.K2(K:K) C39.L2(F:L)
N$194: C39.P2(F:P) C39.T2(T:T)
N$195: C39.R2(F:R) C39.U2 F07.H2(H:O$1) F07.J2
N$196: B36.S2(S:O$1) F07.D2(H:I$1)
N$197: F07.F2(H:I$3) F16.K2(K:E)
N$198: A02.D2 A05.F2(F:O$1)
N$200: B33.L2(L:O$1) B36.L2(N:I$1)
N$201: A40.F2(F:O$1) B36.H2(K:I$1)
N$202: A37.D2(K:D) A37.M2(K:M)
N$203: A20.T2(T:O) A37.H2(K:H)
OP2: A35.F2(H:D) ; also sheet 3,6,7,9,12
RUN: A05.E2(F:I$1) A35.M2(M:E) B14.N2(N:F) B34.T2
SDF0: F01.E2 ; also sheet 15
SDF1: F01.H2 ; also sheet 15
SDF2: F01.L2 ; also sheet 15
SIF0: E01.L2 ; also sheet 15
SIF1: E01.R2 ; also sheet 15
SIF2: E01.U2 ; also sheet 15
WTE: A34.L2(N:I$2) ; also sheet 1,3,6
WTF: B36.J2(K:I$2) B36.M2(N:I$2) ; also sheet 1,3,5,6,10,12
WTS: A37.J2(K:J) ; also sheet 6
Unconnected: A01.A2 A01.B2 A01.C2 A01.D2 A01.E2 A01.H2 A01.K2 A01.M2 A01.N2 A01.P2 A01.S2 A01.T2 A01.V2 A20.P2(M:I$1) A29.T2 A36.H2(M:H) A36.L2(M:L) A36.R2(V:H) A36.U2(V:L) A37.E2(K:E) A37.F2(K:F) A37.L2(K:L) B01.A2 B01.B2 B01.C2 B01.D2 B01.F2 B01.J2 B01.K2 B01.M2 B01.N2 B01.P2 B01.S2 B01.T2 B01.V2 B09.F2(J:RESET) B09.H2 B09.M2(J:SET) B14.L2(N:D) B18.V2(T:I$1) B19.V2(T:I$1) B20.D2(H:I$1) B21.R2(S:E) B22.V2(T:I$1) B31.P2(M:I$1) B35.M2(J:SET) B38.J2(F:I$1) B38.P2(M:I$1) B38.V2(T:I$1) C01.A2 C01.B2 C01.C2 C01.D2 C01.F2 C01.H2 C01.K2 C01.L2 C01.M2 C01.P2 C01.R2 C01.T2 C01.V2 C37.V2(T:I$1) C38.V2(U:L) C39.D2 C39.S2(T:S) D01.A2 D01.B2 D01.C2 D01.D2 D01.F2 D01.H2 D01.K2 D01.M2 D01.N2 D01.R2 D01.S2 D01.T2 D01.V2 D10.J2(F:I$1) D10.P2(M:I$1) D10.V2(T:I$1) E01.A2 E01.B2 E01.C2 E01.D2 E01.F2 E01.J2 E01.K2 E01.M2 E01.N2 E01.P2 E01.S2 E01.T2 E01.V2 E05.D2 E05.P2(F:P) E05.S2(T:S) E05.T2(T:T) E11.P2(S:I$1) F01.A2 F01.B2 F01.C2 F01.D2 F01.F2 F01.K2 F01.M2 F01.N2 F01.P2 F01.R2 F01.S2 F01.T2 F01.U2 F01.V2

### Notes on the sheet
- Switch Register
- * | *
- *
- *
- * NOTE: This module is not in the
- standard machine.  For Auto Restart
- feature only.  Disable Auto Restart
- by removing the module.
- Control
- D-BS-8S-0-15

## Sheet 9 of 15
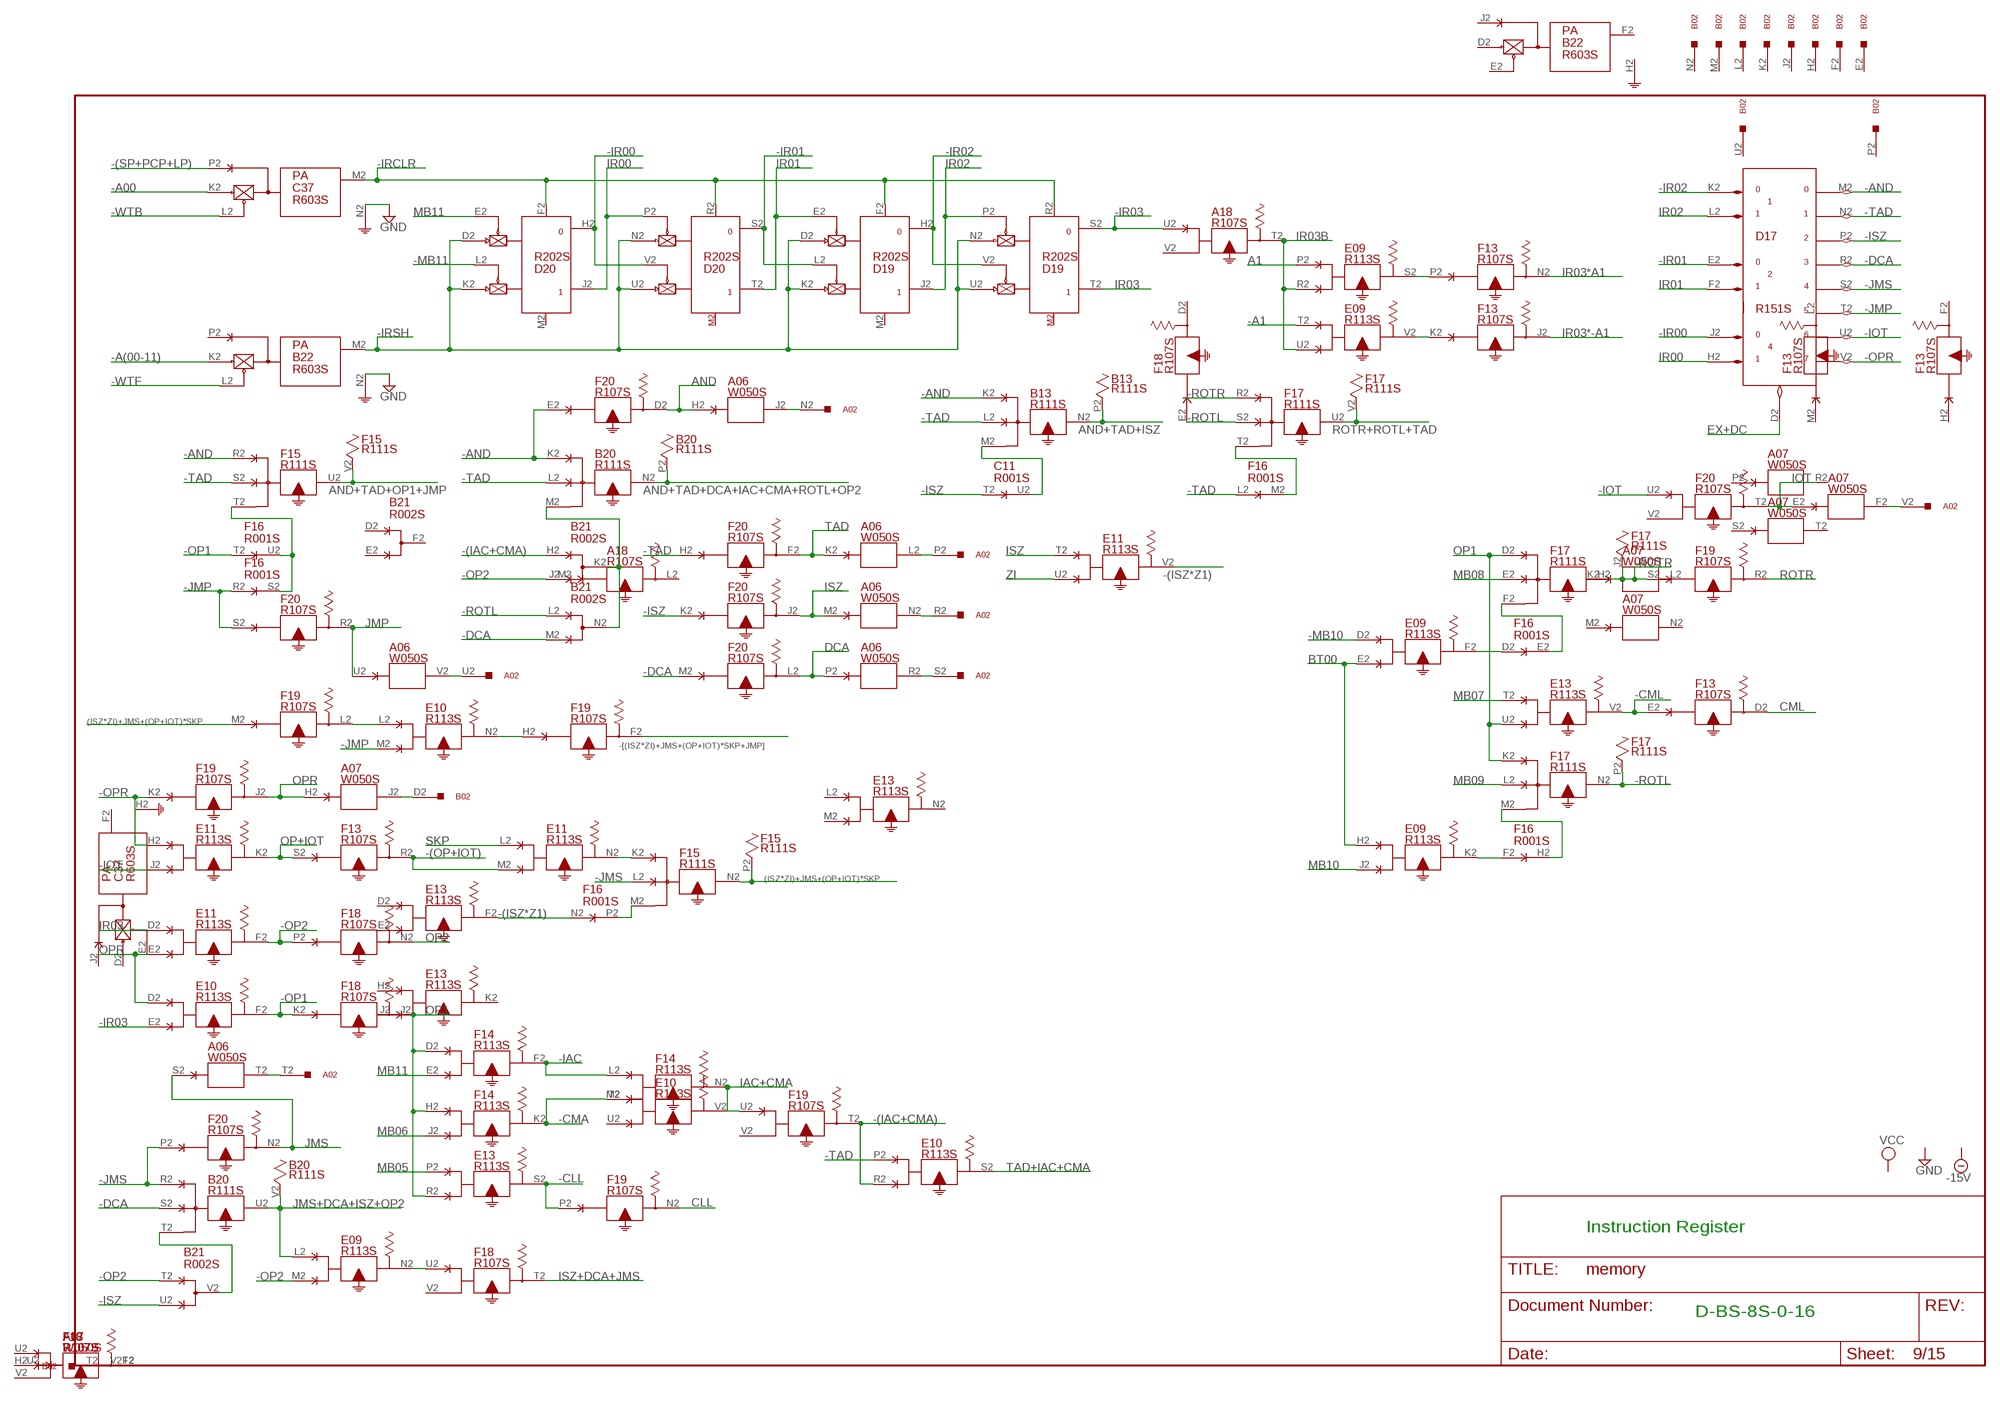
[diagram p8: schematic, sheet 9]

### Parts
A07  W050S  [H807S]
D17  R151S  [H807S]
D19  R202S  [H807S]
D20  R202S  [H807S]
E09  R113S  [H807S]
F14  R113S  [H807S]
F15  R111S  [H807S]
F17  R111S  [H807S]
F19  R107S  [H807S]
F20  R107S  [H807S]

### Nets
(ISZ*ZI)+JMS+(OP+IOT)*SKP: F15.N2(N:O$1) F15.P2 F19.M2(L:I$1) ; also sheet 6
-(IAC+CMA): B21.H2(K:D) E10.R2(S:I$2) F19.T2(T:O$1)
-(ISZ*Z1): E11.V2(V:O$1) F16.N2(P:D)
-(OP+IOT): E11.M2(N:I$2) F13.R2(R:O$1) ; also sheet 1,6
-(SP+PCP+LP): C37.P2(M:I$1) ; also sheet 6,8
-[(ISZ*ZI)+JMS+(OP+IOT)*SKP+JMP]: F19.F2(F:O$1) ; also sheet 6
-A00: C37.K2(M:PU0) ; also sheet 3,4,5,10,14,15
-A1: E09.T2(V:I$1) ; also sheet 6
-A(00-11): B22.K2(M:PU0) ; also sheet 1,3,4,5,7,11,12
-AND: B13.K2(N:I$1) B20.K2(N:I$1) D17.M2(M) F15.R2(U:I$1) F20.E2(D:I$1)
-CLL: E13.S2(S:O$1) F19.P2(N:I$1) ; also sheet 3
-CMA: F14.K2(K:O$1) F14.M2(N:I$2)
-CML: E13.V2(V:O$1) F13.E2(D:I$1) ; also sheet 3
-DCA: B20.S2(U:I$2) B21.M2(N:E) D17.R2(R) F20.M2(L:I$1)
-IAC: F14.F2(F:O$1) F14.L2(N:I$1)
-IOT: D17.U2(U) E11.J2(K:I$2) F20.U2(T:I$1)
-IR00: D17.J2(J) D20.H2 D20.V2(T:EN1)
-IR01: D17.E2(E) D19.L2(J:EN1) D20.S2
-IR02: D17.K2(K) D19.H2 D19.V2(T:EN1)
-IR03: A18.U2(T:I$1) D19.S2 E10.E2(F:I$2) ; also sheet 6
-IRCLR: C37.M2(M:O) D19.F2(J:RESET) D19.R2(T:RESET) D20.F2(J:RESET) D20.R2(T:RESET) ; also sheet 10
-IRSH: B22.M2(M:O) D19.D2(J:PU0) D19.K2(J:PU1) D19.N2(T:PU0) D19.U2(T:PU1) D20.D2(J:PU0) D20.K2(J:PU1) D20.N2(T:PU0) D20.U2(T:PU1)
-ISZ: B21.U2(V:E) C11.T2(U:D) D17.P2(P) F20.K2(J:I$1)
-JMP: D17.T2(T) E10.M2(N:I$2) F16.R2(S:D) F20.S2(R:I$1) ; also sheet 15
-JMS: B20.R2(U:I$1) D17.S2(S) F15.L2(N:I$2) F20.P2(N:I$1) ; also sheet 15
-MB10: E09.D2(F:I$1) ; also sheet 1,2,10
-MB11: D20.L2(J:EN1) ; also sheet 1,2,10
-OP1: E10.F2(F:O$1) F16.T2(U:D) F18.K2(J:I$1)
-OP2: B21.J2(K:E) B21.T2(V:D) E09.M2(N:I$2) E11.F2(F:O$1) F18.P2(N:I$1)
-OPR: D17.V2(V) E11.H2(K:I$1) F19.K2(J:I$1) ; also sheet 1
-ROTL: B21.L2(N:D) F17.N2(N:O$1) F17.P2 F17.S2(U:I$2)
-ROTR: F17.H2(H:O$1) F17.J2 F17.R2(U:I$1) F19.S2(R:I$1) ; also sheet 3
-TAD: B13.L2(N:I$2) B20.L2(N:I$2) D17.N2(N) E10.P2(S:I$1) F15.S2(U:I$2) F16.L2(M:D) F20.H2(F:I$1) ; also sheet 12
-WTB: C37.L2(M:EN0) ; also sheet 6,15
-WTF: B22.L2(M:EN0) ; also sheet 6,7,15
A1: E09.P2(S:I$1) ; also sheet 6
AND: A06.H2(J:I$1) F20.D2(D:O$1) ; also sheet 12
AND+TAD+DCA+IAC+CMA+ROTL+OP2: B20.N2(N:O$1) B20.P2 ; also sheet 12
AND+TAD+ISZ: B13.N2(N:O$1) B13.P2 ; also sheet 1,6
AND+TAD+OP1+JMP: F15.U2(U:O$1) F15.V2 ; also sheet 6
BT00: E09.E2(F:I$2) E09.H2(K:I$1) ; also sheet 4,7,15
CLL: F19.N2(N:O$1) ; also sheet 3
CML: F13.D2(D:O$1) ; also sheet 3
DCA: A06.P2(R:I$1) F20.L2(L:O$1) ; also sheet 6
EX+DC: D17.D2(D) ; also sheet 5,7,8,12
GND [Supply]: B22.N2(M:G) C37.N2(M:G) ; also sheet 1,2,3,4,5,6,7,8,10,11,12,14,15
IAC+CMA: F14.N2(N:O$1) F19.U2(T:I$1) ; also sheet 7,12
IOT: A07.E2(F:I$1) F20.T2(T:O$1) ; also sheet 10,15
IR00: D17.H2(H) D20.J2 D20.P2(T:EN0)
IR01: D17.F2(F) D19.E2(J:EN0) D20.T2
IR02: D17.L2(L) D19.J2 D19.P2(T:EN0)
IR03: D19.T2 E11.D2(F:I$1) ; also sheet 6
IR03*-A1: F13.J2(J:O$1) ; also sheet 6
IR03*A1: F13.N2(N:O$1) ; also sheet 6
IR03B: A18.T2(T:O$1) E09.R2(S:I$2) E09.U2(V:I$2)
ISZ: A06.M2(N:I$1) E11.T2(V:I$1) F20.J2(J:O$1)
ISZ+DCA+JMS: F18.T2(T:O$1) ; also sheet 6
JMP: A06.U2(V:I$1) F20.R2(R:O$1) ; also sheet 6
JMS: A06.S2(T:I$1) F20.N2(N:O$1) ; also sheet 6
JMS+DCA+ISZ+OP2: B20.U2(U:O$1) B20.V2 E09.L2(N:I$1)
MB05: E13.P2(S:I$1) ; also sheet 1,3,10
MB06: F14.J2(K:I$2) ; also sheet 1,3,7
MB07: E13.T2(V:I$1) ; also sheet 1,3
MB08: F17.E2(H:I$2) ; also sheet 1,3,6
MB09: F17.L2(N:I$2) ; also sheet 1,3
MB10: E09.J2(K:I$2) ; also sheet 1,8
MB11: D20.E2(J:EN0) F14.E2(F:I$2) ; also sheet 1,5,6,7,12
N$204: A02.V2 A07.F2(F:O$1)
N$205: A02.N2 A06.J2(J:O$1)
N$206: F15.T2(U:I$3) F16.S2(S:E) F16.U2(U:E)
N$207: B20.M2(N:I$3) B21.K2(K:F) B21.N2(N:F)
N$208: B13.M2(N:I$3) C11.U2(U:E)
N$209: A02.P2 A06.L2(L:O$1)
N$210: E09.S2(S:O$1) F13.P2(N:I$1)
N$211: F16.M2(M:E) F17.T2(U:I$3)
N$212: E09.V2(V:O$1) F13.K2(J:I$1)
N$213: A02.R2 A06.N2(N:O$1)
N$214: F16.E2(E:E) F17.F2(H:I$3)
N$215: F16.H2(H:E) F17.M2(N:I$3)
N$216: A02.U2 A06.V2(V:O$1)
N$217: E09.F2(F:O$1) F16.D2(E:D)
N$218: E09.K2(K:O$1) F16.F2(H:D)
N$219: E10.L2(N:I$1) F19.L2(L:O$1)
N$220: A07.J2(J:O$1) B02.D2
N$221: E11.N2(N:O$1) F15.K2(N:I$1)
N$222: E10.N2(N:O$1) F19.H2(F:I$1)
N$223: B20.T2(U:I$3) B21.V2(V:F)
N$224: A02.T2 A06.T2(T:O$1)
N$225: F15.M2(N:I$3) F16.P2(P:E)
N$226: A02.S2 A06.R2(R:O$1)
N$227: E09.N2(N:O$1) F18.U2(T:I$1)
OP1: E13.R2(S:I$2) E13.U2(V:I$2) F14.D2(F:I$1) F14.H2(K:I$1) F17.D2(H:I$1) F17.K2(N:I$1) F18.J2(J:O$1) ; also sheet 6,7,12
OP2: F18.N2(N:O$1) ; also sheet 3,6,7,8,12
OP+IOT: E11.K2(K:O$1) F13.S2(R:I$1)
OPR: A07.H2(J:I$1) E10.D2(F:I$1) E11.E2(F:I$2) F19.J2(J:O$1)
ROTR: F19.R2(R:O$1) ; also sheet 6
ROTR+ROTL+TAD: F17.U2(U:O$1) F17.V2 ; also sheet 3,12
SKP: E11.L2(N:I$1) ; also sheet 3
TAD: A06.K2(L:I$1) F20.F2(F:O$1) ; also sheet 6
TAD+IAC+CMA: E10.S2(S:O$1) ; also sheet 3,12
ZI: E11.U2(V:I$2) ; also sheet 3,7
Unconnected: A18.V2(T:I$2) D19.M2(J:SET) D20.M2(J:SET) F13.V2(T:I$2) F15.J2 F20.V2(T:I$2)

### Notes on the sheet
- Instruction Register
- D-BS-8S-0-16

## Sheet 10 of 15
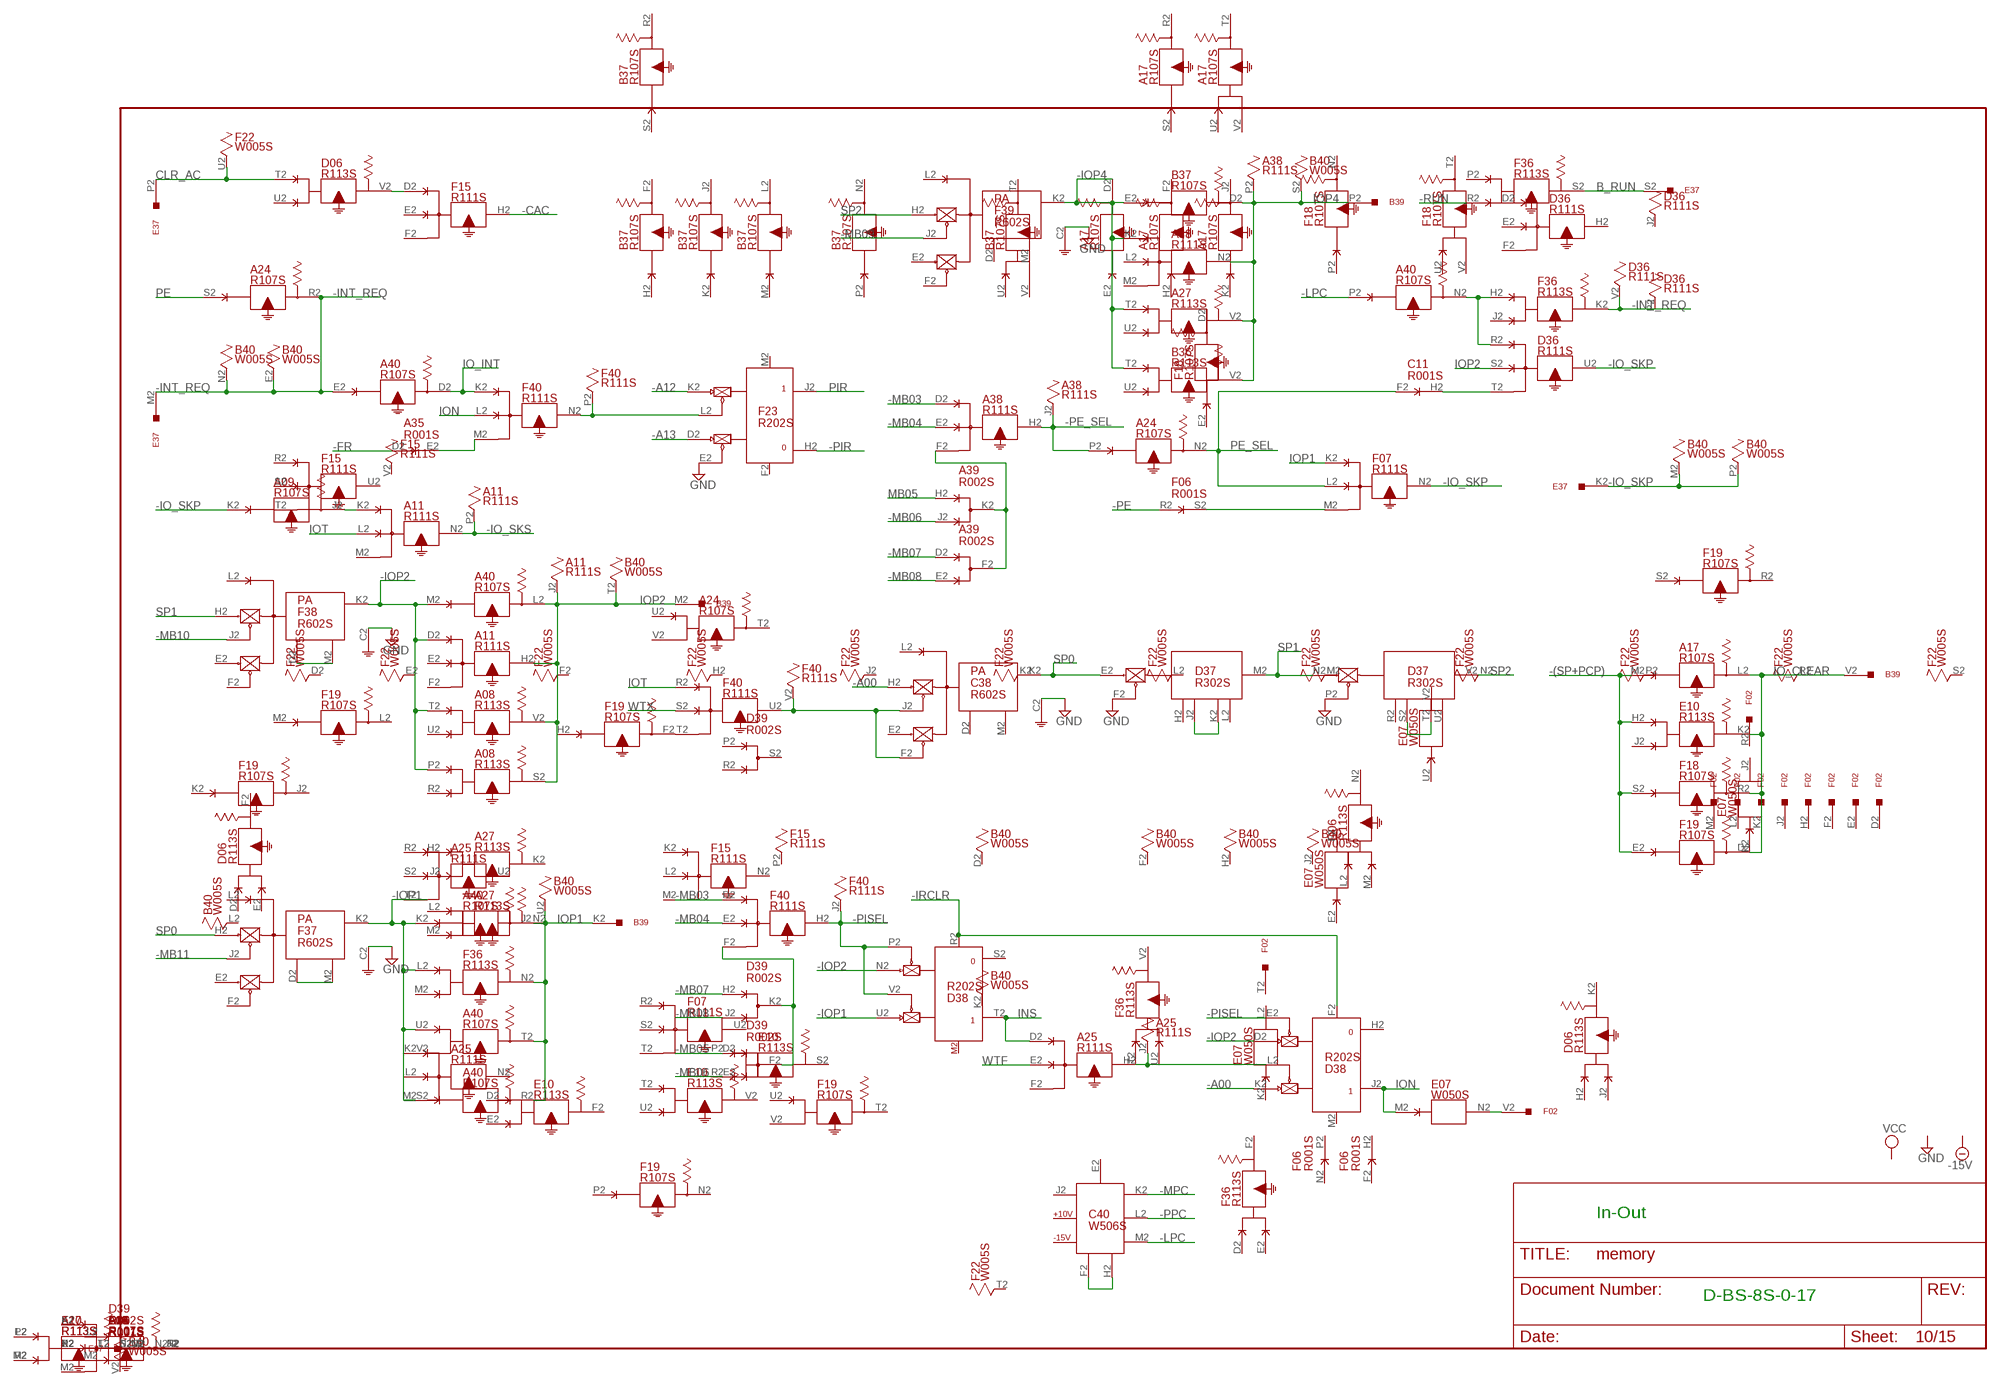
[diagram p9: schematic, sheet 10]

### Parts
A11  R111S  [H807S]
B39  W028S  [H807S]
C40  W506S  [H807S]
D36  R111S  [H807S]
D37  R302S  [H807S]
D38  R202S  [H807S]
D39  R002S  [H807S]
F23  R202S  [H807S]
F40  R111S  [H807S]

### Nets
-(SP+PCP): A17.M2(L:I$1) E10.H2(K:I$1) F18.S2(R:I$1) F19.E2(D:I$1) ; also sheet 1,3,7,8,12,14,15
-A00: C38.H2(K:H) D38.K2(J:PU1) ; also sheet 3,4,5,9,14,15
-A12: F23.K2(J:PU1) ; also sheet 1,3,4,6,8,12,15
-A13: F23.D2(J:PU0) ; also sheet 1,4,5,6,7,15
-CAC: F15.H2(H:O$1) ; also sheet 12
-FR: A35.D2(E:D) ; also sheet 14
-INT_REQ: A24.R2(R:O$1) A40.E2(D:I$1) B40.E2 B40.N2 D36.V2 E37.M2 F36.K2(K:O$1)
-IO_SKP: A09.K2(J:I$1) B40.M2 B40.P2 D36.U2(U:O$1) E37.K2 F07.N2(N:O$1)
-IO_SKS: A11.N2(N:O$1) A11.P2 ; also sheet 3
-IOP1: A40.K2(J:I$1) A40.S2(R:I$1) A40.U2(T:I$1) D38.U2(T:PU1) F36.L2(N:I$1) F37.K2(K:K)
-IOP2: A08.P2(S:I$1) A08.T2(V:I$1) A11.D2(H:I$1) A40.M2(L:I$1) D38.D2(J:PU0) D38.N2(T:PU0) F38.K2(K:K) ; also sheet 14
-IOP4: A27.T2(V:I$1) A38.K2(N:I$1) B36.T2(V:I$1) B37.E2(D:I$1) F39.K2(K:K) ; also sheet 1
-IRCLR: D38.F2(J:RESET) D38.R2(T:RESET) ; also sheet 9
-LPC: A40.P2(N:I$1) C40.M2(M) ; also sheet 8
-MB03: A38.D2(H:I$1) F40.D2(H:I$1) ; also sheet 1,2
-MB04: A38.E2(H:I$2) F40.E2(H:I$2) ; also sheet 1,2,5
-MB05: D39.D2(F:D) ; also sheet 1,2,6
-MB06: A39.J2(K:E) D39.E2(F:E) ; also sheet 1,2,6,7
-MB07: A39.D2(F:D) D39.H2(K:D) ; also sheet 1,2,6
-MB08: A39.E2(F:E) D39.J2(K:E) ; also sheet 1,2,3
-MB09: F39.J2(K:J) ; also sheet 1,2
-MB10: F38.J2(K:J) ; also sheet 1,2,9
-MB11: F37.J2(K:J) ; also sheet 1,2,9
-MPC: C40.K2(K) ; also sheet 13,14
-PE: F06.R2(S:D) ; also sheet 1
-PE_SEL: A24.P2(N:I$1) A38.H2(H:O$1) A38.J2 ; also sheet 1
-PIR: F23.H2 ; also sheet 6
-PISEL: D38.E2(J:EN0) D38.P2(T:EN0) D38.V2(T:EN1) F40.H2(H:O$1) F40.J2
-PPC: C40.L2(L) ; also sheet 4,6,8,11,15
-RUN: F36.R2(S:I$2) ; also sheet 4,8
B_RUN: E37.S2 F36.S2(S:O$1)
CLR_AC: D06.T2(V:I$1) E37.P2 F22.U2
GND [Supply]: C38.C2(K:GND) D37.F2(M:F) D37.P2(V:F) F23.E2(J:EN0) F37.C2(K:GND) F38.C2(K:GND) F39.C2(K:GND) ; also sheet 1,2,3,4,5,6,7,8,9,11,12,14,15
INS: A25.D2(H:I$1) D38.T2
IO_CLEAR: A17.L2(L:O$1) B39.V2 E10.K2(K:O$1) F18.R2(R:O$1) F19.D2(D:O$1)
IO_INT: A40.D2(D:O$1) F40.K2(N:I$1)
ION: D38.J2 E07.M2(N:I$1) F40.L2(N:I$2)
IOP1: A40.J2(J:O$1) A40.R2(R:O$1) A40.T2(T:O$1) B39.K2 B40.U2 F07.K2(N:I$1) F36.N2(N:O$1)
IOP2: A08.S2(S:O$1) A08.V2(V:O$1) A11.H2(H:O$1) A11.J2 A40.L2(L:O$1) B39.M2 B40.T2 D36.S2(U:I$2)
IOP4: A27.V2(V:O$1) A38.N2(N:O$1) A38.P2 B36.V2(V:O$1) B37.D2(D:O$1) B39.P2 B40.S2
IOT: A11.L2(N:I$2) F40.R2(U:I$1) ; also sheet 9,15
MB05: A39.H2(K:D) ; also sheet 1,3,9
N$228: F23.L2(J:EN1) F40.N2(N:O$1) F40.P2
N$229: D06.V2(V:O$1) F15.D2(H:I$1)
N$230: A35.E2(E:E) F40.M2(N:I$3)
N$231: F38.D2(K:D) F38.M2(K:M)
N$232: A09.J2(J:O$1) A11.K2(N:I$1)
N$233: A25.H2(H:O$1) A25.J2 D38.L2(J:EN1)
N$234: E07.N2(N:O$1) F02.V2
N$235: F37.D2(K:D) F37.M2(K:M)
N$236: D39.F2(F:F) D39.K2(K:F) F40.F2(H:I$3)
N$237: C40.F2(F) C40.H2(H)
N$238: C38.F2(K:F) C38.J2(K:J) F40.U2(U:O$1) F40.V2
N$239: D37.J2(M:J) D37.K2(M:K)
N$240: D37.S2(V:J) D37.T2(V:K)
N$241: F06.S2(S:E) F07.M2(N:I$3)
N$242: C11.H2(H:E) D36.T2(U:I$3)
N$243: A38.F2(H:I$3) A39.F2(F:F) A39.K2(K:F)
N$244: A40.N2(N:O$1) D36.R2(U:I$1) F36.H2(K:I$1)
PE: A24.S2(R:I$1) ; also sheet 1
PE_SEL: A24.N2(N:O$1) C11.F2(H:D) F07.L2(N:I$2)
PIR: F23.J2 ; also sheet 6
SP0: C38.K2(K:K) D37.E2(M:E) F37.H2(K:H)
SP1: D37.M2(M:M) D37.N2(V:E) F38.H2(K:H)
SP2: D37.V2(V:M) F39.H2(K:H)
WTF: A25.E2(H:I$2) ; also sheet 1,3,5,6,8,12
WTX: F40.S2(U:I$2) ; also sheet 1,3,6,7,12,15
Unconnected: A08.R2(S:I$2) A08.U2(V:I$2) A11.E2(H:I$2) A11.F2(H:I$3) A11.M2(N:I$3) A11.V2 A17.V2(T:I$2) A24.V2(T:I$2) A25.F2(H:I$3) A27.U2(V:I$2) A38.L2(N:I$2) A38.M2(N:I$3) A40.V2(T:I$2) B36.U2(V:I$2) B37.V2(T:I$2) B39.S2 B39.T2 C38.D2(K:D) C38.E2(K:E) C38.L2(K:L) C38.M2(K:M) C40.E2(E) C40.J2(J) D06.U2(V:I$2) D37.H2(M:H) D37.L2(M:L) D37.R2(V:H) D37.U2(V:L) D38.H2 D38.M2(J:SET) D38.S2 E10.J2(K:I$2) F07.T2(U:I$3) F15.E2(H:I$2) F15.F2(H:I$3) F18.V2(T:I$2) F19.V2(T:I$2) F23.F2(J:RESET) F23.M2(J:SET) F23.N2(T:PU0) F23.P2(T:EN0) F23.R2(T:RESET) F23.S2 F23.T2 F23.U2(T:PU1) F23.V2(T:EN1) F36.J2(K:I$2) F36.M2(N:I$2) F36.P2(S:I$1) F37.E2(K:E) F37.F2(K:F) F37.L2(K:L) F38.E2(K:E) F38.F2(K:F) F38.L2(K:L) F39.D2(K:D) F39.E2(K:E) F39.F2(K:F) F39.L2(K:L) F39.M2(K:M) F40.T2(U:I$3)

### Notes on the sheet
- In-Out
- D-BS-8S-0-17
